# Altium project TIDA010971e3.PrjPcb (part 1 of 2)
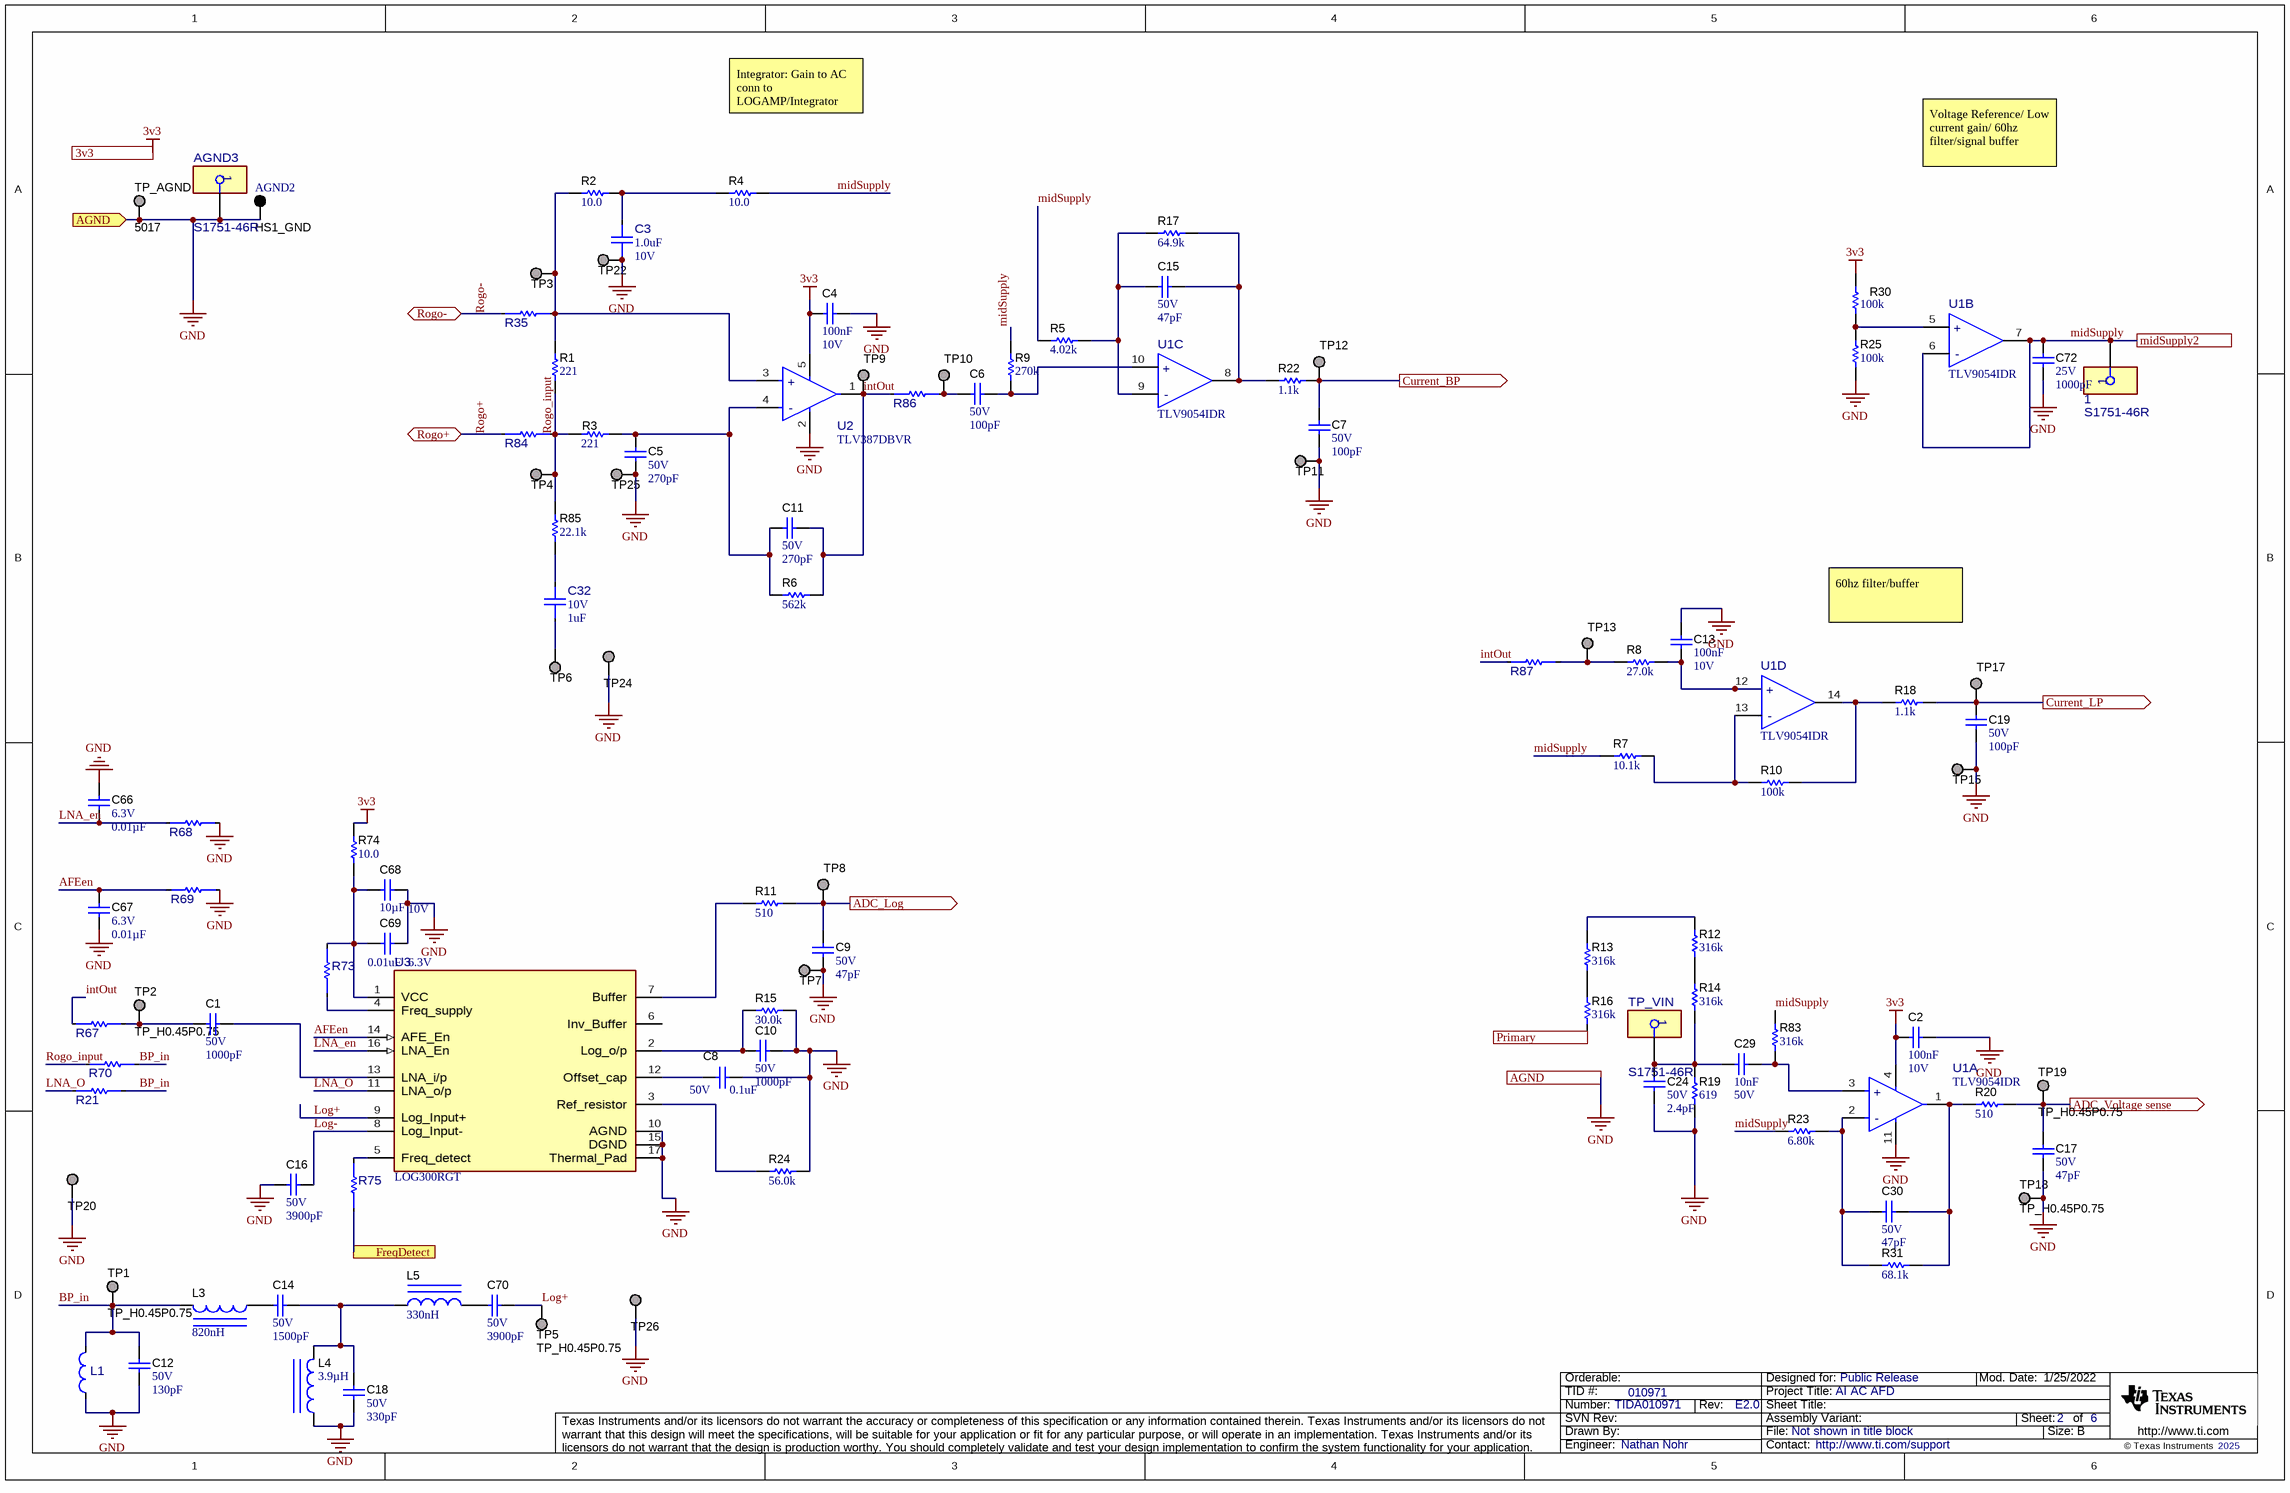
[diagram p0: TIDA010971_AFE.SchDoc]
CopyrightYear: 2025; PCB_Layout: Nathan Nohr; PCB_Rev: E2.2; PRJ_Customer: Public Release; PRJ_Engineer: Nathan Nohr; PRJ_Number: TIDA010971; PRJ_Title: AI AC AFD; SCH_Rev: E2.0; TechSupport: http://www.ti.com/support; TID: 010971
5 sheets, 285 parts. Net scope: flat (ports and power ports of the same name join across sheets).
Board file: TIDA010971_.PcbDoc
Sheets:
  TIDA010971_AFE.SchDoc
  TIDA010971_Hardware.SchDoc
  TIDA010971_Power.SchDoc
  TIDA010971_Connectors_MCU_Labeling.SchDoc
  TIDA010971_AutoLabeling.SchDoc

## Sheet TIDA010971_AFE.SchDoc
size 431 x 279 mm; Date: Not shown in title block; ApprovedBy: Not shown in title block; CheckedBy: Not shown in title block; Author: Not shown in title block; CompanyName: Not shown in title block; Engineer: Not shown in title block; Organization: Not shown in title block; Address1: Not shown in title block; Address2: Not shown in title block; Address3: Not shown in title block; Address4: Not shown in title block; DocumentNumber: 2; Revision: Use project parameter SCH_Rev; SheetNumber: 2; SheetTotal: 6; PageSetup: Record=PageOptions¦CenterHorizontal=True¦CenterVertical=True¦PrintScale=1.00¦XCorrection=1.00¦YCorrection=1.00¦PrintKind=0¦BorderSize=5000000¦LeftOffset=0¦BottomOffset=0¦Orientation=2¦PaperLength=1000¦PaperWidth=1000¦Scale=100¦PaperSource=15¦PrintQuality=600¦MediaType=1¦DitherType=10¦PaperKind=Letter¦PrintScaleMode=1

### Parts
1  S1751-46R  [FP-S1751-46R_SMT_TEST_POINT_3MM25_1MM65-MFG]
AGND2  HS1_GND  [Keystone5006]
AGND3  S1751-46R  [FP-S1751-46R_SMT_TEST_POINT_3MM25_1MM65-MFG]
C1  VDC_V: 50V  ValueDisplayed: 1000pF  [0603]  (hidden comment: GRM1885C1H102JA01D)
C2  Cap_F: 100nF  VDC_V: 10V  [0603]  (hidden comment: 0603ZC104KAT2A)
C3  ValueDisplayed: 1.0uF  VDC_V: 10V  [FP-GRM155Z71A105KE01J_0402-MFG]  (hidden comment: GRM155Z71A105KE01J)
C4  Cap_F: 100nF  VDC_V: 10V  [0603]  (hidden comment: 0603ZC104KAT2A)
C5  VDC_V: 50V  ValueDisplayed: 270pF  [0603]  (hidden comment: C0603C271J5GACTU)
C6  VDC_V: 50V  ValueDisplayed: 100pF  [0603]  (hidden comment: 06035A101JAT2A)
C7  VDC_V: 50V  ValueDisplayed: 100pF  [0603]  (hidden comment: 06035A101JAT2A)
C8  value 0.1uF  VDC_V: 50V  [0603]  (hidden comment: 06035C104JAT2A)
C9  VDC_V: 50V  ValueDisplayed: 47pF  [0603]  (hidden comment: GRM1885C1H470JA01D)
C10  VDC_V: 50V  ValueDisplayed: 1000pF  [0603]  (hidden comment: GRM1885C1H102JA01D)
C11  VDC_V: 50V  ValueDisplayed: 270pF  [0603]  (hidden comment: C0603C271J5GACTU)
C12  VDC_V: 50V  ValueDisplayed: 130pF  [0603]  (hidden comment: GRM1885C1H131JA01D)
C13  Cap_F: 100nF  VDC_V: 10V  [0603]  (hidden comment: 0603ZC104KAT2A)
C14  VDC_V: 50V  ValueDisplayed: 1500pF  [0603]  (hidden comment: GRM1885C1H152JA01D)
C15  VDC_V: 50V  ValueDisplayed: 47pF  [0603]  (hidden comment: 06035A470JAT2A)
C16  VDC_V: 50V  ValueDisplayed: 3900pF  [0402]  (hidden comment: CL05B392KB5NNNC)
C17  VDC_V: 50V  ValueDisplayed: 47pF  [0603]  (hidden comment: GRM1885C1H470JA01D)
C18  VDC_V: 50V  ValueDisplayed: 330pF  [0603]  (hidden comment: GRM1885C1H331JA01D)
C19  VDC_V: 50V  ValueDisplayed: 100pF  [0603]  (hidden comment: 06035A101JAT2A)
C24  VDC_V: 50V  ValueDisplayed: 2.4pF  [0402]  (hidden comment: GRM1555C1H2R4CA01D)
C29  Cap_F: 10nF  VDC_V: 50V  [0603]  (hidden comment: CL10B103KB8NCNC)
C30  VDC_V: 50V  ValueDisplayed: 47pF  [0603]  (hidden comment: GRM1885C1H470JA01D)
C32  VDC_V: 10V  ValueDisplayed: 1uF  [FP-GMC04X7R105K10NT_0402-MFG]  (hidden comment: GMC04X7R105K10NT)
C66  VDC_V: 6.3V  ValueDisplayed: 0.01µF  [0402]  (hidden comment: 0402B103K6R3CT)
C67  VDC_V: 6.3V  ValueDisplayed: 0.01µF  [0402]  (hidden comment: 0402B103K6R3CT)
C68  Cap_F: 10µF  VDC_V: 10V  [0603]  (hidden comment: GRM188Z71A106MA73D)
C69  VDC_V: 6.3V  ValueDisplayed: 0.01uF  [0402]  (hidden comment: GRM155R70J103KA01D)
C70  VDC_V: 50V  ValueDisplayed: 3900pF  [0402]  (hidden comment: CL05B392KB5NNNC)
C72  VDC_V: 25V  ValueDisplayed: 1000pF  [0402]  (hidden comment: C0402C102J3GACTU)
L1  BSCY00160808100MCP  [FP-BSCY00160808100MCP_0603-MFG]  (value not drawn)
L3  ValueDisplayed: 820nH  [0603AF]  (hidden comment: 0603AF-821KRB)
L4  ValueDisplayed: 3.9µH  [0603LS_B2]  (hidden comment: 0603LS-392XJLB)
L5  ValueDisplayed: 330nH  [0603LS_B1]  (hidden comment: 0603LS-331XJLB)
R1  ValueDisplayed: 221  [0603]  (hidden comment: RT0603BRD07221RL)
R2  ValueDisplayed: 10.0  [0603]  (hidden comment: CRCW060310R0FKEAHP)
R3  ValueDisplayed: 221  [0603]  (hidden comment: RG1608P-2210-B-T5)
R4  ValueDisplayed: 10.0  [0603]  (hidden comment: CRCW060310R0FKEAHP)
R5  ValueDisplayed: 4.02k  [0603]  (hidden comment: RT0603DRE074K02L)
R6  ValueDisplayed: 562k  [0603]  (hidden comment: RT0603BRD07562KL)
R7  ValueDisplayed: 10.1k  [0603]  (hidden comment: RT0603DRE0710K1L)
R8  ValueDisplayed: 27.0k  [0603]  (hidden comment: ERJ-3EKF2702V)
R9  ValueDisplayed: 270k  [0603]  (hidden comment: RC0603FR-07270KL)
R10  ValueDisplayed: 100k  [0603]  (hidden comment: CRCW0603100KJNEAC)
R11  ValueDisplayed: 510  [0603]  (hidden comment: RG1608P-511-B-T5)
R12  ValueDisplayed: 316k  [0805_HV1]  (hidden comment: CRCW0805316KFKEA)
R13  ValueDisplayed: 316k  [0805_HV1]  (hidden comment: CRCW0805316KFKEA)
R14  ValueDisplayed: 316k  [0805_HV1]  (hidden comment: CRCW0805316KFKEA)
R15  ValueDisplayed: 30.0k  [0603]  (hidden comment: RC0603FR-0730KL)
R16  ValueDisplayed: 316k  [0805_HV1]  (hidden comment: CRCW0805316KFKEA)
R17  ValueDisplayed: 64.9k  [0603]  (hidden comment: RT0603DRE0764K9L)
R18  ValueDisplayed: 1.1k  [0603]  (hidden comment: CRCW06031K10JNEA)
R19  ValueDisplayed: 619  [0603]  (hidden comment: RC0603FR-07619RL)
R20  ValueDisplayed: 510  [0603]  (hidden comment: RG1608P-511-B-T5)
R21  RC0603FR-100RL  [FP-RC0603FR-100RL_0603-MFG]  (value not drawn)
R22  ValueDisplayed: 1.1k  [0603]  (hidden comment: CRCW06031K10JNEA)
R23  ValueDisplayed: 6.80k  [0603]  (hidden comment: RC0603FR-076K8L)
R24  ValueDisplayed: 56.0k  [0603]  (hidden comment: RG1608P-563-B-T5)
R25  ValueDisplayed: 100k  [0603]  (hidden comment: CRCW0603100KJNEAC)
R30  ValueDisplayed: 100k  [0603]  (hidden comment: CRCW0603100KJNEAC)
R31  ValueDisplayed: 68.1k  [0603]  (hidden comment: RC0603FR-0768K1L)
R35  RC0603FR-100RL  [FP-RC0603FR-100RL_0603-MFG]  (value not drawn)
R67  RC0603FR-100RL  [FP-RC0603FR-100RL_0603-MFG]  (value not drawn)
R68  RC0603FR-100RL  [FP-RC0603FR-100RL_0603-MFG]  (value not drawn)
R69  RC0603FR-100RL  [FP-RC0603FR-100RL_0603-MFG]  (value not drawn)
R70  RC0603FR-100RL  [FP-RC0603FR-100RL_0603-MFG]  (value not drawn)
R73  RC0603FR-100RL  [FP-RC0603FR-100RL_0603-MFG]  (value not drawn)
R74  ValueDisplayed: 10.0  [0402]  (hidden comment: MCR01MZPF10R0)
R75  RC0603FR-100RL  [FP-RC0603FR-100RL_0603-MFG]  (value not drawn)
R83  ValueDisplayed: 316k  [0603]  (hidden comment: RC0603FR-07316KL)
R84  RC0603FR-100RL  [FP-RC0603FR-100RL_0603-MFG]  (value not drawn)
R85  ValueDisplayed: 22.1k  [0603L]  (hidden comment: CRCW060322K1FKEA)
R86  RC0603FR-100RL  [FP-RC0603FR-100RL_0603-MFG]  (value not drawn)
R87  RC0603FR-100RL  [FP-RC0603FR-100RL_0603-MFG]  (value not drawn)
TP1  TP_H0.45P0.75  [TP_H045P075]  (no BOM)
TP2  TP_H0.45P0.75  [TP_H045P075]  (no BOM)
TP3  TP_H0.45P0.75  [TP_H045P075]  (value not drawn)  (no BOM)
TP4  TP_H0.45P0.75  [TP_H045P075]  (value not drawn)  (no BOM)
TP5  TP_H0.45P0.75  [TP_H045P075]  (no BOM)
TP6  TP_H0.45P0.75  [TP_H045P075]  (value not drawn)  (no BOM)
TP7  TP_H0.45P0.75  [TP_H045P075]  (value not drawn)  (no BOM)
TP8  TP_H0.45P0.75  [TP_H045P075]  (value not drawn)  (no BOM)
TP9  TP_H0.45P0.75  [TP_H045P075]  (value not drawn)  (no BOM)
TP10  TP_H0.45P0.75  [TP_H045P075]  (value not drawn)  (no BOM)
TP11  TP_H0.45P0.75  [TP_H045P075]  (value not drawn)  (no BOM)
TP12  TP_H0.45P0.75  [TP_H045P075]  (value not drawn)  (no BOM)
TP13  TP_H0.45P0.75  [TP_H045P075]  (value not drawn)  (no BOM)
TP15  TP_H0.45P0.75  [TP_H045P075]  (value not drawn)  (no BOM)
TP17  TP_H0.45P0.75  [TP_H045P075]  (value not drawn)  (no BOM)
TP18  TP_H0.45P0.75  [TP_H045P075]  (no BOM)
TP19  TP_H0.45P0.75  [TP_H045P075]  (no BOM)
TP20  TP_H0.45P0.75  [TP_H045P075]  (value not drawn)  (no BOM)
TP22  TP_H0.45P0.75  [TP_H045P075]  (value not drawn)  (no BOM)
TP24  TP_H0.45P0.75  [TP_H045P075]  (value not drawn)  (no BOM)
TP25  TP_H0.45P0.75  [TP_H045P075]  (value not drawn)  (no BOM)
TP26  TP_H0.45P0.75  [TP_H045P075]  (value not drawn)  (no BOM)
TP_AGND  5017  [Keystone_5017]
TP_VIN  S1751-46R  [FP-S1751-46R_SMT_TEST_POINT_3MM25_1MM65-MFG]
U1  TLV9054IDR  [D0014A-MFG]  (parts A,B,C,D of 4)
U2  TLV387DBVR  [DBV0005A-MFG]
U3  LOG300RGT  [RGT0016A-MFG]

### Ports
3v3, ADC_Log (out), ADC_Voltage sense (out), AGND, AGND (in), Current_BP (out), Current_LP (out), FreqDetect, midSupply2, Primary, Rogo+ (bidir), Rogo- (bidir)

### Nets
3v3: C2.2 C4.2 R30.2 R74.2 U1.4(V+) U2.5(V+) ; port 3v3
GND: AGND2.1 AGND3.1 C2.1 C3.1 C4.1 C5.1 C7.2 C8.1 C9.2 C10.1 C12.2 C13.1 C16.2 C17.2 C18.2 C19.2 C24.2 C66.1 C67.2 C68.1 C69.1 C72.2 L1.1 L4.1 R15.1 R19.1 R24.2 R25.1 R68.2 R69.1 TP7.1 TP11.1 TP15.1 TP18.1 TP20.1 TP22.1 TP24.1 TP25.1 TP26.1 TP_AGND.1 U1.11(V-) U2.2(V-) U3.10(AGND) U3.15(DGND) U3.17(Thermal_Pad) ; port AGND  [project net AGND]
ADC_Log: C9.1 R11.2 TP8.1 ; port ADC_Log
ADC_Voltage sense: C17.1 R20.2 TP19.1 ; port ADC_Voltage sense
AFEen: C67.1 R69.2 U3.14(AFE_En)
BP_in: C12.1 L1.2 L3.2 R21.2 R70.2 TP1.1
Current_BP: C7.1 R22.2 TP12.1 ; port Current_BP
Current_LP: C19.1 R18.2 TP17.1 ; port Current_LP
FreqDetect: R75.1 ; port FreqDetect
intOut: C11.1 R6.2 R67.1 R86.1 R87.1 TP9.1 U2.1(OUT)
LNA_en: C66.2 R68.1 U3.16(LNA_En)
LNA_O: R21.1 U3.11(LNA_o/p)
Log+: C70.1 TP5.1 U3.9(Log_Input+)
Log-: C16.1 U3.8(Log_Input-)
midSupply: 1.1 C72.1 R4.2 R5.1 R7.1 R9.2 R23.1 R83.2 U1.6(IN2-) U1.7(OUT2) ; port midSupply2
Primary: R16.2 ; port Primary
Rogo+: R84.1 ; port Rogo+
Rogo-: R35.1 ; port Rogo-
Rogo_input: R1.1 R3.1 R70.1 R84.2 R85.2 TP4.1
NetC1_1: C1.1 U3.13(LNA_i/p)
NetC1_2: C1.2 R67.2 TP2.1
NetC3_2: C3.2 R2.2 R4.1
NetC5_2: C5.2 C11.2 R3.2 R6.1 U2.4(-IN)
NetC6_1: C6.1 R9.1 U1.10(IN3+)
NetC6_2: C6.2 R86.2 TP10.1
NetC8_2: C8.2 U3.12(Offset_cap)
NetC10_2: C10.2 R15.2 U3.2(Log_o/p)
NetC13_2: C13.2 R8.2 U1.12(IN4+)
NetC14_1: C14.1 C18.1 L4.2 L5.1
NetC14_2: C14.2 L3.1
NetC15_1: C15.1 R17.2 R22.1 U1.8(OUT3)
NetC15_2: C15.2 R5.2 R17.1 U1.9(IN3-)
NetC24_1: C24.1 C29.2 R14.2 R19.2 TP_VIN.1
NetC29_1: C29.1 R83.1 U1.3(IN1+)
NetC30_1: C30.1 R20.1 R31.2 U1.1(OUT1)
NetC30_2: C30.2 R23.2 R31.1 U1.2(IN1-)
NetC32_1: C32.1 TP6.1
NetC32_2: C32.2 R85.1
NetC68_2: C68.2 C69.2 R73.2 R74.1 U3.1(VCC)
NetC70_2: C70.2 L5.2
NetR1_2: R1.2 R2.1 R35.2 TP3.1 U2.3(+IN)
NetR7_2: R7.2 R10.1 U1.13(IN4-)
NetR8_1: R8.1 R87.2 TP13.1
NetR10_2: R10.2 R18.1 U1.14(OUT4)
NetR11_1: R11.1 U3.7(Buffer)
NetR12_1: R12.1 R13.2
NetR12_2: R12.2 R14.1
NetR13_1: R13.1 R16.1
NetR24_1: R24.1 U3.3(Ref_resistor)
NetR25_2: R25.2 R30.1 U1.5(IN2+)
NetR73_1: R73.1 U3.4(Freq_supply)
NetR75_2: R75.2 U3.5(Freq_detect)

Not connected (* = marked no-connect by the designer): U3 6(Inv_Buffer)

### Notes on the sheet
- Integrator: Gain to AC conn to LOGAMP/Integrator
- Voltage Reference/ Low current gain/ 60hz filter/signal buffer
- 60hz filter/buffer

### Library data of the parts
1 AGND3 TP_VIN = CMP-0089962-1: Natural PC Test Point Brass, Tin Plating Surface Mount Mounting Type; Manufacturer: Harwin; AEC Qualified: No; SizeZ_mm: 2.15mm; Is Female: yes; ContactFinish: Tin,Nickel; Conn Orientation: Vertical; Current_A: 2A
AGND2 = CMP-0055143-2: Test Point, Compact, Black, TH; Manufacturer: Keystone Electronics; CNHeader: FALSE; Green_Lifecycle: Active; Green_REACh: Passed; ContactFinish: Silver; CT: TRUE
C1 C10 = CMP-0007173-4: CAP, CERM, 1000 pF, 50 V, +/- 5%, C0G/NP0, 0603; Manufacturer: MuRata; TaMin_C: -55°C; Polarized: N; SizeAreaWB_mm2: 4.68; Value1: Unknown; U/M: EA; Value: 1000pF; TaMax_C: 125°C; SizeZ_mm: 1; SizeX_mm: 1.6; SizeY_mm: 0.8; SizeArea_mm2: 1.28; Cap_F: 1nF; AEC Category: Q200
C2 C4 C13 = CMP-0006815-4: CAP, CERM, 0.1 uF, 10 V, +/- 10%, X7R, 0603; Manufacturer: AVX; TaMin_C: -55°C; Polarized: N; SizeAreaWB_mm2: 4.68; Value1: Unknown; U/M: EA; Value: 0.1uF; TaMax_C: 125°C; SizeZ_mm: 1; SizeX_mm: 1.6; SizeY_mm: 0.8; SizeArea_mm2: 1.28; AEC Category: Q200
C3 = CMP-0123987-1: Chip Multilayer Ceramic Capacitors for General Purpose, 0402, 1.0uF, X7R, 15%, 10%, 10V; Manufacturer: Murata; AEC Qualified: No; Cap_F: 1µF; SizeZ_mm: 0.6mm; Value: 1µF
C5 C11 = CMP-0006910-4: CAP, CERM, 270 pF, 50 V, +/- 5%, C0G/NP0, 0603; Manufacturer: Kemet; TaMin_C: -55°C; Polarized: N; SizeAreaWB_mm2: 4.68; Value1: Unknown; U/M: EA; Value: 270pF; TaMax_C: 125°C; SizeZ_mm: 1; SizeX_mm: 1.6; SizeY_mm: 0.8; SizeArea_mm2: 1.28; AEC Category: Q200
C6 C7 C19 = CMP-0006763-4: CAP, CERM, 100 pF, 50 V, +/- 5%, C0G/NP0, 0603; Manufacturer: AVX; TaMin_C: -55°C; ESR_ohm: 1.19d; Polarized: N; SizeAreaWB_mm2: 4.68; Value1: 0.119 ohm; U/M: EA; Value: 100pF; TaMax_C: 125°C; SizeZ_mm: 1; SizeX_mm: 1.6; SizeY_mm: 0.8; SizeArea_mm2: 1.28; AEC Category: Q200
C8 = CMP-0083854-1: CAP, CERM, 0.1 µF, 50 V,+/- 5%, X7R, 0603; Manufacturer: AVX; SizeZ_mm: 1; AEC Qualified: N; Cap_F: 100nF; ValueDisplayed: 0.1µF; TaMin_C: -55°C; Green_Lifecycle: Active; SizeAreaWB_mm2: 4.68; Green_REACh: Passed; U/M: EA; TaMax_C: 125°C; SizeX_mm: 1.6; SizeY_mm: 0.8; SizeArea_mm2: 1.28; AEC Category: Q200
C9 C17 C30 = CMP-0007220-4: CAP, CERM, 47 pF, 50 V, +/- 5%, C0G/NP0, 0603; Manufacturer: MuRata; TaMin_C: -55°C; Polarized: N; SizeAreaWB_mm2: 4.68; Value1: Unknown; U/M: EA; Value: 47pF; TaMax_C: 125°C; SizeZ_mm: 1; SizeX_mm: 1.6; SizeY_mm: 0.8; SizeArea_mm2: 1.28; AEC Category: Q200
C12 = CMP-0007182-4: CAP, CERM, 130 pF, 50 V, +/- 5%, C0G/NP0, 0603; Manufacturer: MuRata; TaMin_C: -55°C; Polarized: N; SizeAreaWB_mm2: 4.68; Value1: Unknown; U/M: EA; Value: 130pF; TaMax_C: 125°C; SizeZ_mm: 1; SizeX_mm: 1.6; SizeY_mm: 0.8; SizeArea_mm2: 1.28; AEC Category: Q200
C14 = CMP-0007186-4: CAP, CERM, 1500 pF, 50 V, +/- 5%, C0G/NP0, 0603; Manufacturer: MuRata; TaMin_C: -55°C; Polarized: N; SizeAreaWB_mm2: 4.68; Value1: Unknown; U/M: EA; Value: 1500pF; TaMax_C: 125°C; SizeZ_mm: 1; SizeX_mm: 1.6; SizeY_mm: 0.8; SizeArea_mm2: 1.28; Cap_F: 1.5nF; AEC Category: Q200
C15 = CMP-0006789-4: CAP, CERM, 47 pF, 50 V, +/- 5%, C0G/NP0, 0603; Manufacturer: AVX; TaMin_C: -55°C; ESR_ohm: 1.74d; Polarized: N; SizeAreaWB_mm2: 4.68; Value1: 0.174 ohm; U/M: EA; Value: 47pF; TaMax_C: 125°C; SizeZ_mm: 1; SizeX_mm: 1.6; SizeY_mm: 0.8; SizeArea_mm2: 1.28; AEC Category: Q200
C16 C70 = CMP-0085576-2: CAP, CERM, 3900 pF, 50 V,+/- 10%, X7R, 0402; Manufacturer: Samsung Electro-Mechanics; SizeY_mm: 0.5; AEC Qualified: N; SizeAreaWB_mm2: 3; SizeX_mm: 1; TaMax_C: 125°C; SizeZ_mm: 0.6; Cap_F: 3.9nF; AEC Category: Q200; TaMin_C: -55°C; Value: 3900pF; U/M: EA
C18 = CMP-0007209-4: CAP, CERM, 330 pF, 50 V, +/- 5%, C0G/NP0, 0603; Manufacturer: MuRata; TaMin_C: -55°C; Polarized: N; SizeAreaWB_mm2: 4.68; Value1: Unknown; U/M: EA; Value: 330pF; TaMax_C: 125°C; SizeZ_mm: 1; SizeX_mm: 1.6; SizeY_mm: 0.8; SizeArea_mm2: 1.28; AEC Category: Q200
C24 = CMP-0006449-2: CAP, CERM, 2.4 pF, 50 V, +/- 5%, C0G/NP0, 0402; Manufacturer: MuRata; TaMin_C: -55°C; Polarized: N; SizeAreaWB_mm2: 3; Value1: Unknown; U/M: EA; Value: 2.4pF; TaMax_C: 125°C; SizeZ_mm: 0.6; SizeX_mm: 1; SizeY_mm: 0.5; AEC Category: Q200
C29 = CMP-0007109-5: CAP, CERM, 0.01 uF, 50 V, +/- 10%, X7R, 0603; Manufacturer: Samsung Electro-Mechanics; TaMin_C: -55°C; Polarized: N; SizeAreaWB_mm2: 4.68; Value1: Unknown; U/M: EA; Value: 0.01uF; TaMax_C: 125°C; SizeZ_mm: 1; SizeX_mm: 1.6; SizeY_mm: 0.8; SizeArea_mm2: 1.28; AEC Category: Q200
C32 = CMP-0093200-1: 1µF ±10% 10V Ceramic Capacitor X7R 0402 (1005 Metric); Manufacturer: Cal-Chip Electronics; TempCo: 15%; SizeZ_mm: 0.6mm; AEC Qualified: No
C66 C67 = CMP-0860544-1: CAP, CERM, 0.01 µF, 6.3 V,+/- 10%, X7R, 0402; Manufacturer: Walsin; Value: 0.01uF; SizeY_mm: 0.5; SizeX_mm: 1; SizeZ_mm: 0.6; AEC Category: Q200; SizeAreaWB_mm2: 3; TaMax_C: 125°C; U/M: EA; AEC Qualified: N; Cap_F: 10nF; TaMin_C: -55°C
C68 = CMP-0007497-5: CAP, CERM, 10 uF, 10 V, +/- 20%, X7R, 0603; Manufacturer: MuRata; TaMin_C: -55°C; Polarized: N; SizeAreaWB_mm2: 4.68; Value1: Unknown; U/M: EA; Value: 10uF; TaMax_C: 125°C; SizeZ_mm: 1; SizeX_mm: 1.6; SizeY_mm: 0.8; SizeArea_mm2: 1.28; AEC Category: Q200
C69 = CMP-0006622-2: CAP, CERM, 0.01 uF, 6.3 V, +/- 10%, X7R, 0402; Manufacturer: MuRata; TaMin_C: -55°C; Polarized: N; SizeAreaWB_mm2: 3; Value1: Unknown; U/M: EA; Value: 0.01uF; TaMax_C: 125°C; SizeZ_mm: 0.6; SizeX_mm: 1; SizeY_mm: 0.5; Cap_F: 10nF; AEC Category: Q200
C72 = CMP-0081059-1: CAP, CERM, 1000 pF, 25 V,+/- 5%, C0G/NP0, 0402; Manufacturer: Kemet; TaMin_C: -55°C; Polarized: N; Green_Lifecycle: Active; SizeAreaWB_mm2: 3; Green_REACh: Passed; U/M: EA; Value: 1000pF; TaMax_C: 125°C; SizeZ_mm: 0.6; SizeX_mm: 1; SizeY_mm: 0.5; Cap_F: 1nF; AEC Category: Q200
L1 = CMP-0127583-1: Inductor General Purpose Multi-Layer 10uH 20% 1MHz Ferrite 0.09A 0.9Ohm DCR 0603; Manufacturer: Pulse Electronics; AEC Qualified: No; DCR_ohm: 0.9; Ind_H: 10µH; Irms: 90mA; SizeZ_mm: 1mm
L3 = CMP-0060129-1: Inductor, Wirewound, Ferrite, 820 nH, 0.42 A, 0.579999 ohm, SMD; Manufacturer: Coilcraft; Irms: 0.42A @ 15C rise; Green_Lifecycle: Not Set; SizeAreaWB_mm2: 5.936; DCR_ohm: 5.79999d; Green_REACh: Incomplete; Value: 820nH; Imax_A: 4.2dA; SizeZ_mm: 0.91; SizeX_mm: 1.8; SizeY_mm: 1.12; Value2: 0.42A; SizeArea_mm2: 2.016; AEC Category: Q200
L4 = CMP-0077489-1: Inductor, Wirewound, Ferrite, 3.9 µH, 0.28 A, 1.6 ohm, AEC-Q200 Grade 3, SMD; Manufacturer: Coilcraft; SizeAreaWB_mm2: 6.0732; Irms: 0.28A @ 15C rise; SizeArea_mm2: 2.1042; AEC Qualified: Y; AEC Category: Q200; Value: 3.9uH; SizeZ_mm: 1.12; Imax_A: 2.8dA; AEC Grade: 3; SizeY_mm: 1.169; Value2: 0.28A; Value1: 1.6 ohm; DCR_ohm: 1.6; SizeX_mm: 1.8
L5 = CMP-0077486-1: Inductor, Wirewound, Ferrite, 330 nH, 0.56 A, 0.46 ohm, AEC-Q200 Grade 3, SMD; Manufacturer: Coilcraft; SizeAreaWB_mm2: 5.6448; Irms: 0.56A @ 15C rise; SizeArea_mm2: 1.8288; AEC Qualified: Y; AEC Category: Q200; Value: 330nH; SizeZ_mm: 1.12; Imax_A: 5.6dA; AEC Grade: 3; SizeY_mm: 1.016; Value2: 0.56A; DCR_ohm: 4.6d; SizeX_mm: 1.8
R1 = CMP-0023953-2: RES, 221, 0.1%, 0.1 W, 0603; Manufacturer: Yageo America; Power_W: 100mW; TempCo: 25 ppm/C; Value_Code: 221R; U/M: EA; Value: 221; EIA_Code: E192; SizeX_mm: 1.6; SizeY_mm: 0.8; SizeZ_mm: 1; Value2: 0.1W; SizeArea_mm2: 1.28; VDC_V: 75V; AEC Category: Q200
R2 R4 = CMP-0022004-4: RES, 10.0, 1%, 0.25 W, AEC-Q200 Grade 0, 0603; Manufacturer: Vishay-Dale; Power_W: 250mW; TempCo: 100 ppm/C; Value_Code: 10R0; Value: 10.0; EIA_Code: E96; Res_ohm: 10; SizeX_mm: 1.6; SizeY_mm: 0.8; SizeZ_mm: 1; Value2: 0.25W; SizeArea_mm2: 1.28; AEC Qualified: Y; VDC_V: 75V; AEC Category: Q200; AEC Grade: 0
R3 = CMP-0023468-3: RES, 221, 0.1%, 0.1 W, 0603; Manufacturer: Susumu Co Ltd; Power_W: 100mW; TempCo: 25 ppm/C; Value_Code: 221R; U/M: EA; Value: 221; EIA_Code: E192; SizeX_mm: 1.6; SizeY_mm: 0.8; SizeZ_mm: 1; Value2: 0.1W; SizeArea_mm2: 1.28; VDC_V: 75V; AEC Category: Q200
R5 = CMP-0025335-3: RES, 4.02 k, 0.5%, 0.1 W, 0603; Manufacturer: Yageo America; Power_W: 100mW; TempCo: 50 ppm/C; Value_Code: 4k02; U/M: EA; Value: 4.02k; EIA_Code: E192; SizeX_mm: 1.6; SizeY_mm: 0.8; SizeZ_mm: 1; Value2: 0.1W; SizeArea_mm2: 1.28; VDC_V: 75V; AEC Category: Q200
R6 = CMP-0024341-3: RES, 562 k, 0.1%, 0.1 W, 0603; Manufacturer: Yageo America; Power_W: 100mW; TempCo: 25 ppm/C; U/M: EA; Value: 562k; EIA_Code: E192; SizeX_mm: 1.6; SizeY_mm: 0.8; SizeZ_mm: 1; Value2: 0.1W; SizeArea_mm2: 1.28; VDC_V: 75V; AEC Category: Q200
R7 = CMP-0024579-2: RES, 10.1 k, 0.5%, 0.1 W, 0603; Manufacturer: Yageo America; Power_W: 100mW; TempCo: 50 ppm/C; Value_Code: 10k1; U/M: EA; Value: 10.1k; EIA_Code: E192; SizeX_mm: 1.6; SizeY_mm: 0.8; SizeZ_mm: 1; Value2: 0.1W; SizeArea_mm2: 1.28; VDC_V: 75V; AEC Category: Q200
R8 = CMP-0022694-3: RES, 27.0 k, 1%, 0.1 W, AEC-Q200 Grade 0, 0603; Manufacturer: Panasonic; Power_W: 100mW; TempCo: 100 ppm/C; Value_Code: 27k0; U/M: EA; Value: 27.0k; Res_ohm: 27k; SizeX_mm: 1.6; SizeY_mm: 0.8; SizeZ_mm: 1; Value2: 0.1W; SizeArea_mm2: 1.28; AEC Qualified: Y; VDC_V: 50V; AEC Grade: 0; AEC Category: Q200
R9 = CMP-0022961-4: RES, 270 k, 1%, 0.1 W, 0603; Manufacturer: Yageo; Power_W: 100mW; TempCo: 100 ppm/C; Value: 270k; SizeX_mm: 1.6; SizeY_mm: 0.8; SizeZ_mm: 1; Value2: 0.1W; SizeArea_mm2: 1.28; AEC Qualified: N; VDC_V: 75V; AEC Category: Q200; SizeAreaWB_mm2: 4.68
R10 R25 R30 = CMP-0082530-1: RES, 100 k, 5%, 0.1 W, 0603; Manufacturer: Vishay-Dale; Power_W: 100mW; TempCo: 200 ppm/C; SizeAreaWB_mm2: 4.68; Value: 100k; EIA_Code: E24; SizeX_mm: 1.6; SizeY_mm: 0.8; SizeZ_mm: 1; Value2: 0.1W; SizeArea_mm2: 1.28; AEC Qualified: N; VDC_V: 75V; AEC Category: Q200
R11 R20 = CMP-0023567-3: RES, 510, 0.1%, 0.1 W, 0603; Manufacturer: Susumu Co Ltd; Power_W: 100mW; TempCo: 25 ppm/C; Value_Code: 510R; U/M: EA; Value: 510; SizeX_mm: 1.6; SizeY_mm: 0.8; SizeZ_mm: 1; Value2: 0.1W; SizeArea_mm2: 1.28; VDC_V: 75V; AEC Category: Q200
R12-R14 R16 = CMP-0021166-3: RES, 316 k, 1%, 0.125 W, AEC-Q200 Grade 0, 0805; Manufacturer: Vishay-Dale; Power_W: 125mW; TempCo: 100 ppm/C; Value: 316k; EIA_Code: E96; SizeX_mm: 2; SizeY_mm: 1.25; SizeZ_mm: 1.45; Value2: 0.125W; SizeArea_mm2: 2.5; AEC Qualified: Y; VDC_V: 150V; AEC Category: Q200; AEC Grade: 0
R15 = CMP-0023020-5: RES, 30.0 k, 1%, 0.1 W, 0603; Manufacturer: Yageo; Power_W: 100mW; TempCo: 100 ppm/C; Value_Code: 30k0; Value: 30.0k; Res_ohm: 30k; SizeX_mm: 1.6; SizeY_mm: 0.8; SizeZ_mm: 1; Value2: 0.1W; SizeArea_mm2: 1.28; AEC Qualified: N; VDC_V: 75V; AEC Category: Q200; SizeAreaWB_mm2: 4.68
R17 = CMP-0025488-3: RES, 64.9 k, 0.5%, 0.1 W, 0603; Manufacturer: Yageo America; Power_W: 100mW; TempCo: 50 ppm/C; Value_Code: 64k9; U/M: EA; Value: 64.9k; EIA_Code: E192; SizeX_mm: 1.6; SizeY_mm: 0.8; SizeZ_mm: 1; Value2: 0.1W; SizeArea_mm2: 1.28; VDC_V: 75V; AEC Category: Q200
R18 R22 = CMP-0025730-4: RES, 1.1 k, 5%, 0.1 W, AEC-Q200 Grade 0, 0603; Manufacturer: Vishay-Dale; Power_W: 100mW; TempCo: 200 ppm/C; Value_Code: 1k10; Value: 1.1k; EIA_Code: E24; SizeX_mm: 1.6; SizeY_mm: 0.8; SizeZ_mm: 1; Value2: 0.1W; SizeArea_mm2: 1.28; AEC Qualified: Y; VDC_V: 75V; AEC Category: Q200; AEC Grade: 0
R19 = CMP-0023215-5: RES, 619, 1%, 0.1 W, 0603; Manufacturer: Yageo; Power_W: 100mW; TempCo: 100 ppm/C; Value_Code: 619R; Value: 619; EIA_Code: E96; SizeX_mm: 1.6; SizeY_mm: 0.8; SizeZ_mm: 1; Value2: 0.1W; SizeArea_mm2: 1.28; AEC Qualified: N; VDC_V: 75V; AEC Category: Q200; SizeAreaWB_mm2: 4.68
R21 R35 R67-R70 R73 R75 R84 R86 R87 = CMP-0123755-1: 0 Ohms Jumper Chip Resistor 0603 (1608 Metric) Moisture Resistant Thick Film; Manufacturer: Yageo; AEC Qualified: No; Res_ohm: 0; SizeZ_mm: 0.55mm; Tolerance_%: 1%; Value: 0
R23 = CMP-0023253-5: RES, 6.80 k, 1%, 0.1 W, 0603; Manufacturer: Yageo; Power_W: 100mW; TempCo: 100 ppm/C; Value_Code: 6k80; Value: 6.80k; Res_ohm: 6.8k; SizeX_mm: 1.6; SizeY_mm: 0.8; SizeZ_mm: 1; Value2: 0.1W; SizeArea_mm2: 1.28; AEC Qualified: N; VDC_V: 75V; AEC Category: Q200; SizeAreaWB_mm2: 4.68
R24 = CMP-0023577-3: RES, 56.0 k, 0.1%, 0.1 W, 0603; Manufacturer: Susumu Co Ltd; Power_W: 100mW; TempCo: 25 ppm/C; Value_Code: 56k0; U/M: EA; Value: 56.0k; Res_ohm: 56k; SizeX_mm: 1.6; SizeY_mm: 0.8; SizeZ_mm: 1; Value2: 0.1W; SizeArea_mm2: 1.28; VDC_V: 75V; AEC Category: Q200
R31 = CMP-0023238-5: RES, 68.1 k, 1%, 0.1 W, 0603; Manufacturer: Yageo; Power_W: 100mW; TempCo: 100 ppm/C; Value_Code: 68k1; Value: 68.1k; EIA_Code: E96; SizeX_mm: 1.6; SizeY_mm: 0.8; SizeZ_mm: 1; Value2: 0.1W; SizeArea_mm2: 1.28; AEC Qualified: N; VDC_V: 75V; AEC Category: Q200; SizeAreaWB_mm2: 4.68
R74 = CMP-0026717-1: RES, 10.0, 1%, 0.063 W, 0402; Manufacturer: Rohm; Power_W: 63mW; TempCo: 100 ppm/C; Value_Code: 10R0; U/M: EA; Value: 10.0; EIA_Code: E96; Res_ohm: 10; SizeX_mm: 1; SizeY_mm: 0.5; SizeZ_mm: 0.6; Value2: 0.063W; AEC Qualified: N; VDC_V: 50V; AEC Category: Q200
R83 = CMP-0023024-4: RES, 316 k, 1%, 0.1 W, 0603; Manufacturer: Yageo; Power_W: 100mW; TempCo: 100 ppm/C; Value: 316k; EIA_Code: E96; SizeX_mm: 1.6; SizeY_mm: 0.8; SizeZ_mm: 1; Value2: 0.1W; SizeArea_mm2: 1.28; AEC Qualified: N; VDC_V: 75V; AEC Category: Q200; SizeAreaWB_mm2: 4.68
R85 = CMP-0022220-4: RES, 22.1 k, 1%, 0.1 W, AEC-Q200 Grade 0, 0603; Manufacturer: Vishay-Dale; Power_W: 100mW; TempCo: 100 ppm/C; Value_Code: 22k1; Value: 22.1k; EIA_Code: E96; SizeX_mm: 1.6; SizeY_mm: 0.8; SizeZ_mm: 1; Value2: 0.1W; SizeArea_mm2: 1.28; AEC Qualified: Y; VDC_V: 75V; AEC Category: Q200; AEC Grade: 0
TP1-TP13 TP15 TP17-TP20 TP22 TP24-TP26 = CMP-0003719-1: Testpoint; Manufacturer: Texas Instruments; CompType: Pad
TP_AGND = CMP-0078225-3: PC Test Point, SMT; Manufacturer: Keystone Electronics
U1 = CMP-0125179-1: Quad 5-MHz, 15-V/µs high slew-rate, RRIO op amp 14-SOIC -40 to 125; Manufacturer: Texas Instruments; SizeZ_mm: 1.75mm; AEC Qualified: No; Gain Bandwidth: 5MHz; Input Bias Current: 2pA; Input Offset Voltage: 0.33mV; Max Dual Supply Voltage: 3V; Max Supply Voltage: 6V; Min Dual Supply Voltage: 900mV; Min Supply Voltage: 1.8V; Nominal Supply Current: 330uA; Number Of Channels: 4; Output Current Per Channel: 50mA; Response Time: 1us; Standoff Height: 0.1mm; TaMax_C: +125°C; TaMin_C: -40°C; TJmax_C: +150°C; Voltage Gain: 130dB
U2 = CMP-0125353-1: Zero-Drift Amplifier 1 Circuit Rail-to-Rail SOT-23-5; Manufacturer: Texas Instruments; SizeZ_mm: 1.45mm; AEC Qualified: No; Gain Bandwidth: 5.7MHz; Input Bias Current: 60pA; Input Offset Voltage: 1.25uV; Max Dual Supply Voltage: 2.75V; Max Supply Voltage: 5.5V; Min Dual Supply Voltage: 850mV; Min Supply Voltage: 1.7V; Nominal Supply Current: 570uA; Number Of Channels: 1; Output Current Per Channel: 55mA; Response Time: 2.5us; Standoff Height: 0mm; TaMax_C: +125°C; TaMin_C: -40°C; TJmax_C: +150°C; Voltage Gain: 145dB
U3 = CMP-0122050-1: 80-MHz, Logarithmic Detector With Integrated Low-Noise Amplifier; Manufacturer: Texas Instruments; SizeZ_mm: 1mm; AEC Qualified: No; Bandwidth: 79.9999MHz; Max Supply Voltage: 5.25V; Min Supply Voltage: 3V; Standoff Height: 0mm; TaMax_C: +125°C; TaMin_C: -40°C; TJmax_C: +150°C

## Sheet TIDA010971_Hardware.SchDoc
size 431 x 279 mm; Date: Not shown in title block; ApprovedBy: Not shown in title block; CheckedBy: Not shown in title block; Author: Not shown in title block; CompanyName: Not shown in title block; Engineer: Not shown in title block; Organization: Not shown in title block; Address1: Not shown in title block; Address2: Not shown in title block; Address3: Not shown in title block; Address4: Not shown in title block; DocumentNumber: 3; Revision: Use project parameter SCH_Rev; SheetNumber: 3; SheetTotal: 6; PageSetup: Record=PageOptions¦CenterHorizontal=True¦CenterVertical=True¦PrintScale=1.00¦XCorrection=1.00¦YCorrection=1.00¦PrintKind=0¦BorderSize=5000000¦LeftOffset=0¦BottomOffset=0¦Orientation=2¦PaperLength=1000¦PaperWidth=1000¦Scale=100¦PaperSource=15¦PrintQuality=600¦MediaType=1¦DitherType=10¦PaperKind=Letter¦PrintScaleMode=1
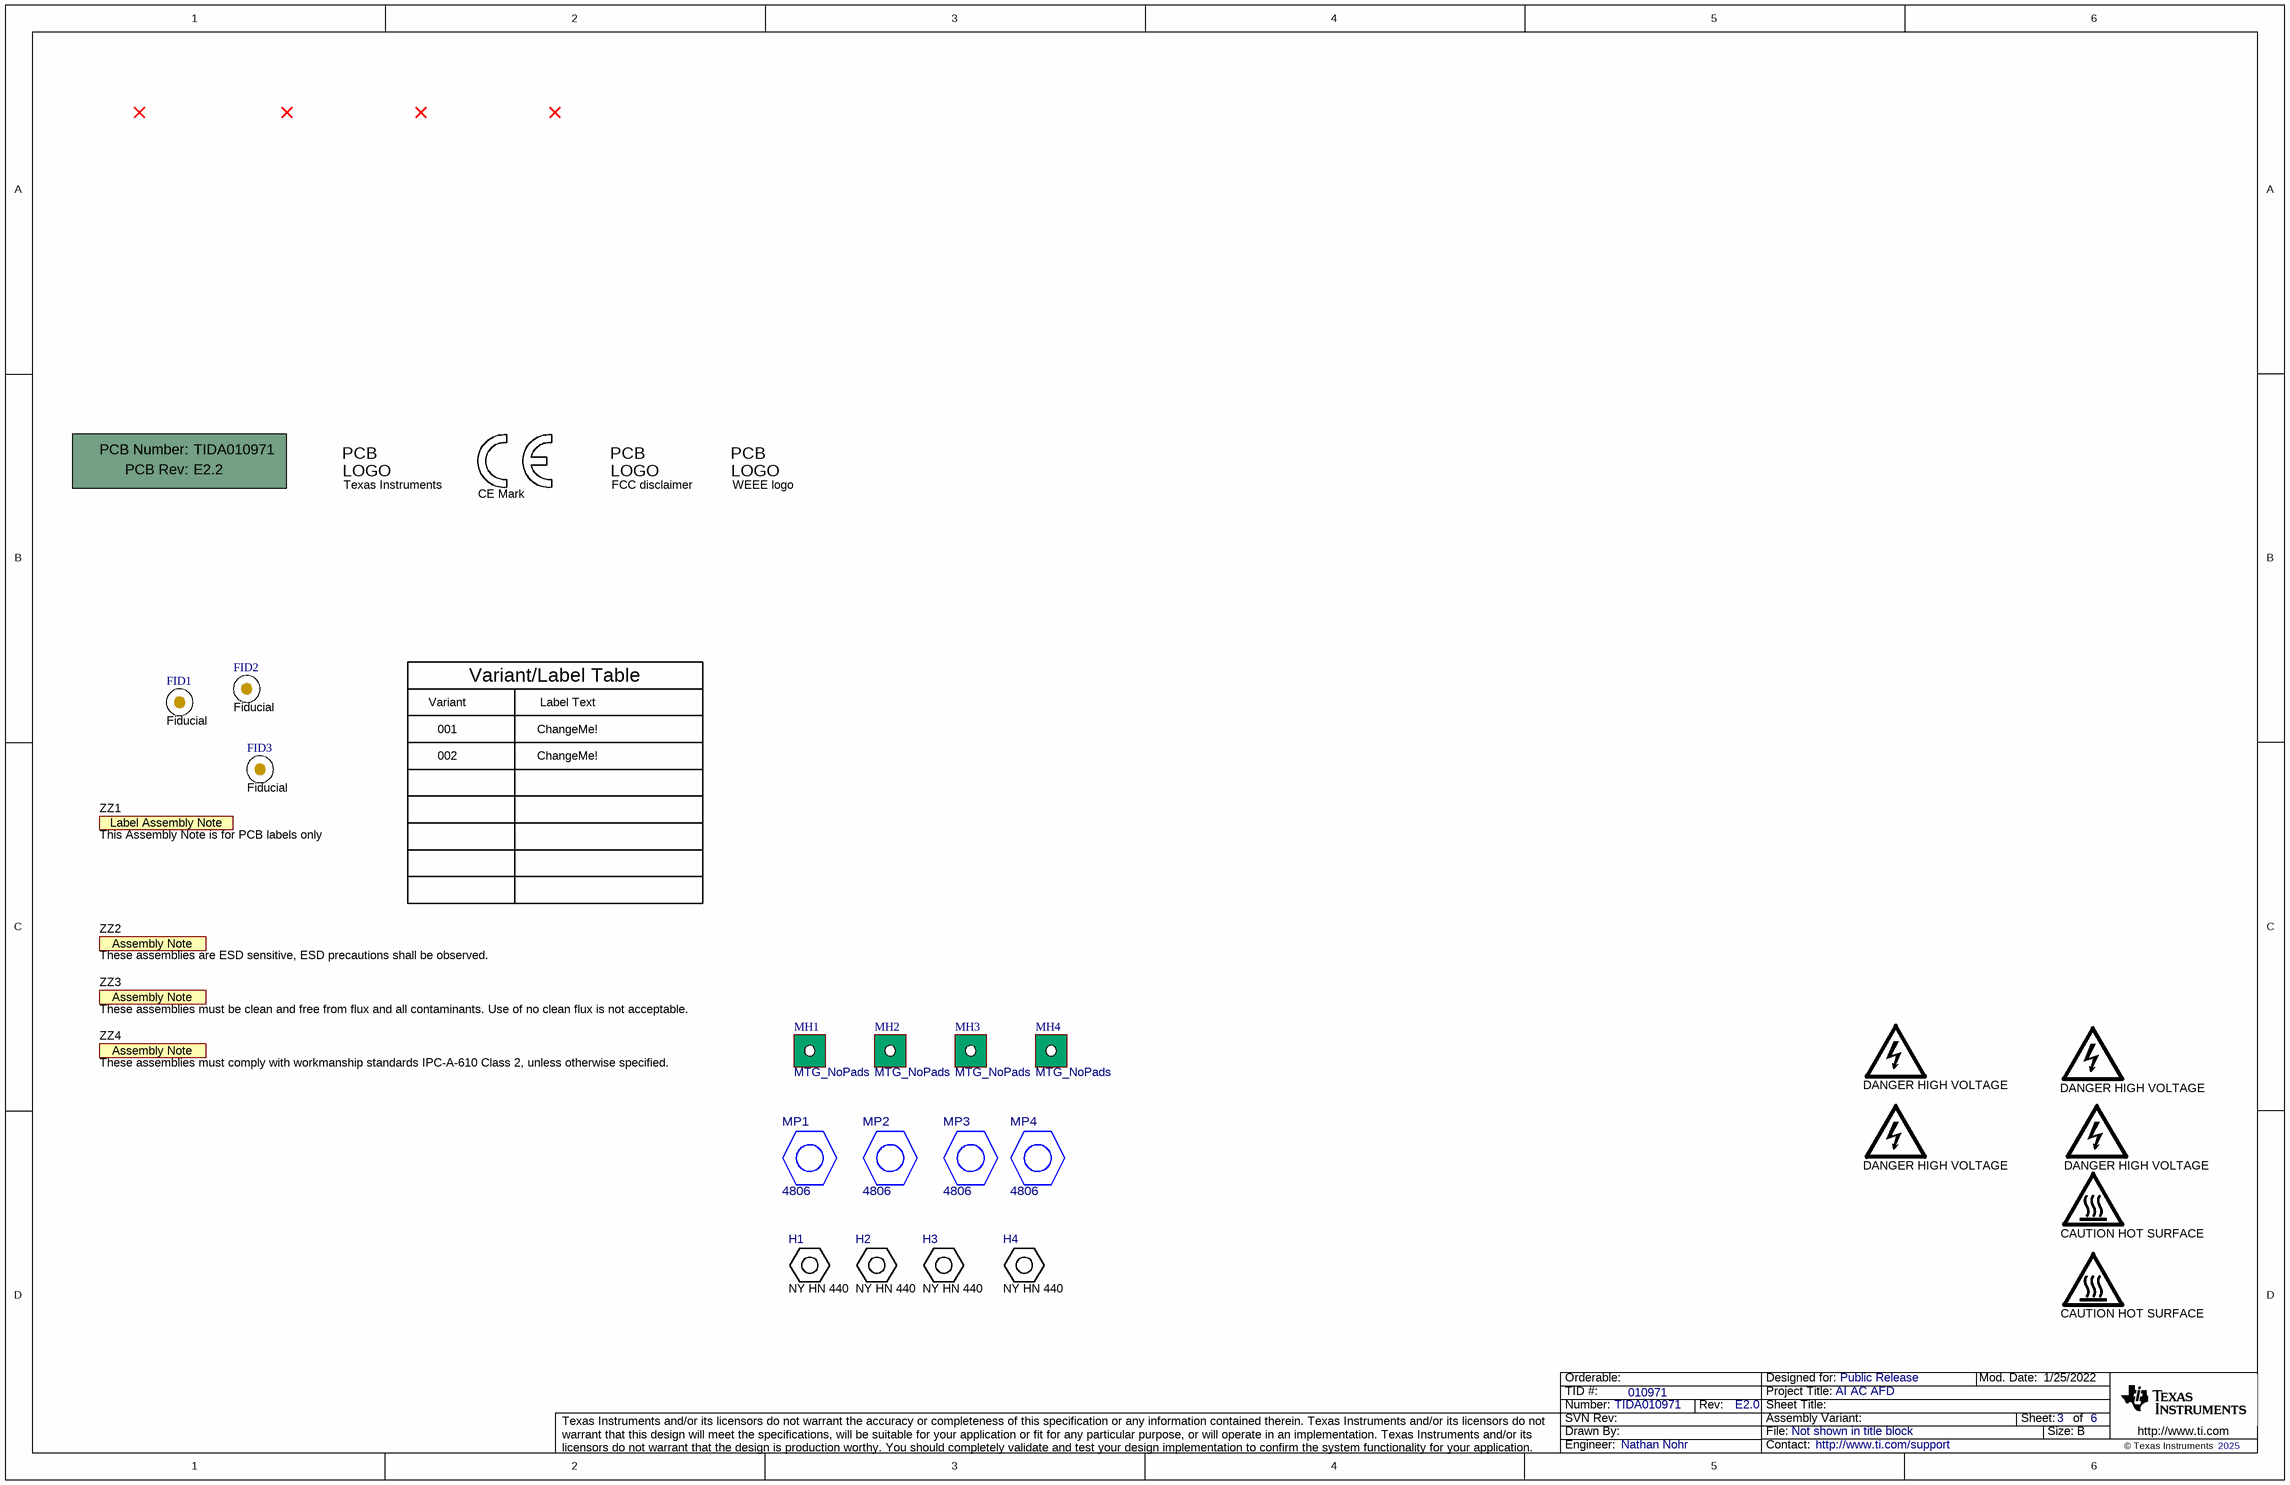
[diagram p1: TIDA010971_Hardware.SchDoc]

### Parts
!PCB  Printed Circuit Board  (value not drawn)  (mechanical)
FID1  Fiducial  [Fiducial10-30]
FID2  Fiducial  [Fiducial10-30]
FID3  Fiducial  [Fiducial10-30]
H1  NY HN 440  (mechanical)
H2  NY HN 440  (mechanical)
H3  NY HN 440  (mechanical)
H4  NY HN 440  (mechanical)
Logo1  Texas Instruments  [TI_Stacked_Overlay_Small]  (no BOM)
Logo2  CE Mark  [CE_Mark_5mm]  (no BOM)
Logo3  FCC disclaimer  [FCC_disclaimer]  (no BOM)
Logo4  WEEE logo  [WEEE_Minimum]  (no BOM)
LOGO5  DANGER HIGH VOLTAGE  [IEC_HighVoltage_Small]  (no BOM)
LOGO6  DANGER HIGH VOLTAGE  [IEC_HighVoltage_Small]  (no BOM)
LOGO7  CAUTION HOT SURFACE  [IEC_HotSurface_Small]  (no BOM)
LOGO8  DANGER HIGH VOLTAGE  [IEC_HighVoltage_Small]  (no BOM)
LOGO9  CAUTION HOT SURFACE  [IEC_HotSurface_Small]  (no BOM)
LOGO10  DANGER HIGH VOLTAGE  [IEC_HighVoltage_Small]  (no BOM)
MH1  MTG_NoPads  [NPTH125mil]  (no BOM)
MH2  MTG_NoPads  [NPTH125mil]  (no BOM)
MH3  MTG_NoPads  [NPTH125mil]  (no BOM)
MH4  MTG_NoPads  [NPTH125mil]  (no BOM)
MP1  4806  [FP-4806_HEX_STNDFF_4-40-MFG]
MP2  4806  [FP-4806_HEX_STNDFF_4-40-MFG]
MP3  4806  [FP-4806_HEX_STNDFF_4-40-MFG]
MP4  4806  [FP-4806_HEX_STNDFF_4-40-MFG]
ZZ1  This Assembly Note is for PCB labels only  [AssemblyNoteLabel]  (no BOM)
ZZ2  These assemblies are ESD sensitive, ESD precautions shall be observed.  [AssemblyNote]  (no BOM)
ZZ3  These assemblies must be clean and free from flux and all contaminants. Use of no clean flux is not acceptable.  [AssemblyNote]  (no BOM)
ZZ4  These assemblies must comply with workmanship standards IPC-A-610 Class 2, unless otherwise specified.  [AssemblyNote]  (no BOM)

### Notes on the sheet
- Variant
- Variant/Label Table
- Label Text
- 001
- 002
- ChangeMe!

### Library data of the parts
!PCB = CMP-0003618-2: Manufacturer: Any; PartNumber: TIDA010971
FID1-FID3 = CMP-0077181-1: Fiducial mark.  There is nothing to buy or mount.
H1-H4 = CMP-0003666-1: Nut, Hex, 4-40, Nylon; Manufacturer: B&F Fastener Supply; CompType: Hardware
Logo1 = CMP-0074838-1: Texas Instrument Corporate Signature; SymbolCreator: a0412235; Lib Reference: TI_Logo; Library Reference: Logo
Logo2 = CMP-0074844-1: SymbolCreator: a0412235
Logo3 = CMP-0074847-1: FCC_disclaimer; Library Reference: Logo
Logo4 = CMP-0074769-1
LOGO5 LOGO6 LOGO8 LOGO10 = CMP-0074835-1: IEC 61010-1 High Voltage Warning; SymbolCreator: a0412235; Lib Reference: IEC_HighVoltage
LOGO7 LOGO9 = CMP-0074837-1: IEC 61010-1 Hot Surface Warning; SymbolCreator: a0412235; Lib Reference: IEC_HotSurface
MH1-MH4 = CMP-0078424-2: PCB Mounting Hole, No Pad; Manufacturer: Any; Key: Mounting Hole (non-standard) No Pad
MP1-MP4 = CMP-0122442-1: Hex Standoff Threaded #4-40 Nylon 1.000" (25.40mm) 1" Natural; Manufacturer: Keystone; AEC Qualified: No; SizeZ_mm: 25.78mm
ZZ1 = CMP-0003616-3
ZZ2 = CMP-0077236-1
ZZ3 = CMP-0077237-1
ZZ4 = CMP-0077238-1

## Sheet TIDA010971_Power.SchDoc
size 431 x 279 mm; Date: Not shown in title block; ApprovedBy: Not shown in title block; CheckedBy: Not shown in title block; Author: Not shown in title block; CompanyName: Not shown in title block; Engineer: Not shown in title block; Organization: Not shown in title block; Address1: Not shown in title block; Address2: Not shown in title block; Address3: Not shown in title block; Address4: Not shown in title block; DocumentNumber: 2; Revision: Use project parameter SCH_Rev; SheetNumber: 4; SheetTotal: 6; PageSetup: Record=PageOptions¦CenterHorizontal=True¦CenterVertical=True¦PrintScale=1.00¦XCorrection=1.00¦YCorrection=1.00¦PrintKind=0¦BorderSize=5000000¦LeftOffset=0¦BottomOffset=0¦Orientation=2¦PaperLength=1000¦PaperWidth=1000¦Scale=100¦PaperSource=15¦PrintQuality=600¦MediaType=1¦DitherType=10¦PaperKind=Letter¦PrintScaleMode=1
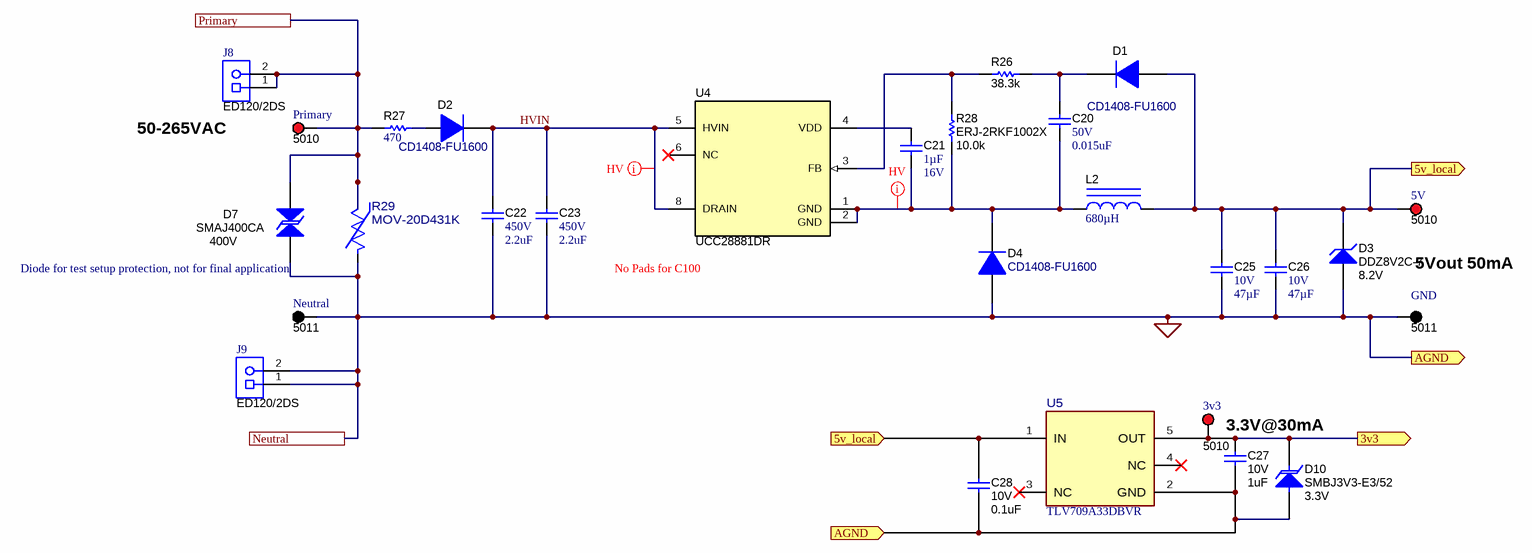
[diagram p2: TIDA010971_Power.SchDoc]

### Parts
3v3  5010  [Keystone5010]
5V  5010  [Keystone5010]
C20  VDC_V: 50V  ValueDisplayed: 0.015uF  [0402S]  (hidden comment: GRM155R71H153KA12D)
C21  ValueDisplayed: 1µF  VDC_V: 16V  [0402]  (hidden comment: GRM155R61C105MA12D)
C22  VDC_V: 450V  ValueDisplayed: 2.2uF  [CKG57N]  (hidden comment: CKG57NX7T2W225M500JH)
C23  VDC_V: 450V  ValueDisplayed: 2.2uF  [CKG57N]  (hidden comment: CKG57NX7T2W225M500JH)
C25  VDC_V: 10V  ValueDisplayed: 47µF  [0805L]  (hidden comment: GRM21BR61A476ME15L)
C26  VDC_V: 10V  ValueDisplayed: 47µF  [0805L]  (hidden comment: GRM21BR61A476ME15L)
C27  VDC_V: 10V  ValueDisplayed: 1uF  [0402S]  (hidden comment: GRM155R61A105ME15D)
C28  VDC_V: 10V  ValueDisplayed: 0.1uF  [0402S]  (hidden comment: GRM155R61A104KA01D)
D1  CD1408-FU1600  [Diode_1408]
D2  CD1408-FU1600  [Diode_1408]
D3  DDZ8V2C-7  value 8.2V  [SOD-123]
D4  CD1408-FU1600  [Diode_1408]
D7  SMAJ400CA  value 400V  [SMA_Bi]
D10  SMBJ3V3-E3/52  value 3.3V  [SMB]
GND  5011  [Keystone5011]
J8  ED120/2DS  [On-Shore_ED120_2DS]
J9  ED120/2DS  [On-Shore_ED120_2DS]
L2  ValueDisplayed: 680µH  [WE-LQ_1812]  (hidden comment: 744045681)
Neutral  5011  [Keystone5011]
Primary  5010  [Keystone5010]
R26  ValueDisplayed: 38.3k  [0402S]  (hidden comment: CRCW040238K3FKED)
R27  ValueDisplayed: 470  [2010L]  (hidden comment: CRCW2010470RFKEF)
R28  ERJ-2RKF1002X  ValueDisplayed: 10.0k  [0402S]
R29  MOV-20D431K  [FP-MOV-20D431K_RADIAL-MFG]
U4  UCC28881DR  [D0007A_N]
U5  TLV709A33DBVR  [DBV0005A-MFG]

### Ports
3v3 (out), 5v_local (in), 5v_local (out), AGND (in), AGND (out), Neutral, Primary

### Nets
3v3: 3v3.1 C27.1 D10.1(K) U5.5(OUT) ; port 3v3
AGND: C22.2 C23.2 C25.2 C26.2 C27.2 C28.2 D3.2(A) D4.2(A) D7.1 D10.2(A) GND.1 J9.1 J9.2 Neutral.1 R29.1 U5.2(GND) ; port AGND, port Neutral
5v_led: 5V.1 C25.1 C26.1 C28.1 D1.2(A) D3.1(K) L2.2 U5.1(IN) ; port 5v_local
HVIN: C22.1 C23.1 D2.1(K) U4.5(HVIN) U4.8(DRAIN)
Primary: D7.2 J8.1 J8.2 Primary.1 R27.1 R29.2 ; port Primary
NetC20_1: C20.1 D1.1(K) R26.2
NetC20_2: C20.2 C21.2 D4.1(K) L2.1 R28.1 U4.1(GND) U4.2(GND)
NetC21_1: C21.1 U4.4(VDD)
NetD2_2: D2.2(A) R27.2
NetR26_1: R26.1 R28.2 U4.3(FB)

Not connected (* = marked no-connect by the designer): U4 6(NC)*; U5 3(NC)* 4(NC)*

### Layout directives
net class HV: HVIN, NetC20_2

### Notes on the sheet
- (near J8) 50-265VAC
- (near R29) Diode for test setup protection, not for final application
- (near U4) No Pads for C100
- 5Vout 50mA
- 3.3V@30mA

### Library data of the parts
3v3 5V Primary = CMP-0055147-2: Test Point, Multipurpose, Red, TH; Manufacturer: Keystone Electronics; CT: TRUE; ContactFinish: Silver; Green_Lifecycle: Active; CNHeader: FALSE; Green_REACh: Passed
C20 = CMP-0006679-2: CAP, CERM, 0.015 uF, 50 V, +/- 10%, X7R, 0402; Manufacturer: MuRata; TaMin_C: -55°C; Polarized: N; SizeAreaWB_mm2: 3; Value1: Unknown; U/M: EA; TaMax_C: 125°C; SizeZ_mm: 0.6; SizeX_mm: 1; SizeY_mm: 0.5; Cap_Case: 0402; Cap_F: 15nF; AEC Category: Q200
C21 = CMP-0084375-1: CAP, CERM, 1 µF, 16 V,+/- 20%, X5R, 0402; Manufacturer: MuRata; SizeX_mm: 1; AEC Category: Q200; SizeAreaWB_mm2: 3; U/M: EA; TaMin_C: -55°C; AEC Qualified: N; SizeZ_mm: 0.6; TaMax_C: 85°C; SizeArea_mm2: 0.5; Value: 1uF
C22 C23 = CMP-0009428-2: CAP, CERM, 2.2 uF, 450 V, +/- 20%, X7T, AEC-Q200 Grade 1, 6x5x5mm; Manufacturer: TDK; TaMin_C: -55°C; Polarized: N; SizeAreaWB_mm2: 56; Value1: Unknown; U/M: EA; Value: 2.2uF; TaMax_C: 125°C; SizeZ_mm: 5.5; SizeX_mm: 6; SizeY_mm: 5; Cap_Case: 2220; SizeArea_mm2: 30; AEC Qualified: Y; Cap_F: 2.2µF; AEC Grade: 1; AEC Category: Q200
C25 C26 = CMP-0078699-1: CAP, CERM, 47 µF, 10 V,+/- 20%, X5R, 0805; Manufacturer: MuRata; TaMin_C: -55°C; Polarized: N; Green_Lifecycle: Active; SizeAreaWB_mm2: 6.75; Green_REACh: Passed; U/M: EA; Value: 47uF; TaMax_C: 85°C; SizeZ_mm: 1.45; SizeX_mm: 2; SizeY_mm: 1.25; Cap_Case: 0805; SizeArea_mm2: 2.5; AEC Category: Q200
C27 = CMP-0064927-2: CAP, CERM, 1 uF, 10 V,+/- 20%, X5R, 0402; Manufacturer: MuRata; TaMin_C: -55°C; Polarized: N; SizeAreaWB_mm2: 3; Value1: Unknown; U/M: EA; Value: 1uF; TaMax_C: 85°C; SizeZ_mm: 0.6; SizeX_mm: 1; SizeY_mm: 0.5; Cap_Case: 0402; Cap_F: 1µF; AEC Category: Q200
C28 = CMP-0006562-2: CAP, CERM, 0.1 uF, 10 V, +/- 10%, X5R, 0402; Manufacturer: MuRata; TaMin_C: -55°C; Polarized: N; SizeAreaWB_mm2: 3; Value1: Unknown; U/M: EA; Value: 0.1uF; TaMax_C: 85°C; SizeZ_mm: 0.6; SizeX_mm: 1; SizeY_mm: 0.5; Cap_Case: 0402; Cap_F: 100nF; AEC Category: Q200
D1 D2 D4 = CMP-0029015-1: Diode, Ultrafast, 600 V, 1 A, 1408 Diode; Manufacturer: Bourns; Io_A: 1A; Green_Lifecycle: Not Set; SizeAreaWB_mm2: 12.76; Vr_V: 600V; Green_REACh: Incomplete; TJmax_C: 175°C; U/M: EA; Value: 600V; SizeZ_mm: 1.15; SizeX_mm: 3.4; SizeY_mm: 1.9; Vf_V: 1.25V; SizeArea_mm2: 6.46; AEC Qualified: N; AEC Category: Q101; RJC_CperW: 40
D3 = CMP-0085110-1: Diode, Zener, 8.2 V, 500 mW, SOD-123; Manufacturer: Diodes Inc.; SizeAreaWB_mm2: 13.095; RJA_CperW: 425; SizeX_mm: 3.85; Value1: 0.5W; AEC Qualified: N; Power_W: 500mW; SizeY_mm: 1.7; AEC Category: Q101; SizeZ_mm: 1.35; SizeArea_mm2: 6.545
D7 = CMP-0085045-1: Diode, TVS, Bi, 400 V, 648 Vc, 400 W, 0.6 A, SMA (non-polarized); Manufacturer: Littelfuse; SizeArea_mm2: 13.068125; SizeAreaWB_mm2: 32.368125; Value1: 648V; Vbr_Min: 447V; AEC Qualified: N; SizeX_mm: 5.075; SizeY_mm: 2.575; Ipp: 600mA; AEC Category: Q101; RJA_CperW: 120; SizeZ_mm: 2.65; Vbr_Max: 494V; Ppk: 400W
D10 = CMP-0005592-3: Diode, TVS, Uni, 3.3 V, 7.3 Vc, AEC-Q101, SMB; Manufacturer: Vishay-Semiconductor; SizeZ_mm: 2.6; Ipp: 50A; Vc: 7.3V; Vbr_Min: 4.1V; SizeY_mm: 3.81; SizeAreaWB_mm2: 44.156; AEC Qualified: Y; SizeArea_mm2: 21.336; RJA_CperW: 100; SizeX_mm: 5.6; Value1: 600W; AEC Category: Q101
GND Neutral = CMP-0055148-2: Test Point, Multipurpose, Black, TH; Manufacturer: Keystone Electronics; CNHeader: FALSE; ContactFinish: Silver; Green_REACh: Passed; Green_Lifecycle: Active; CT: TRUE
J8 J9 = CMP-0074910-1: Terminal Block, 5.08 mm, 2x1, Brass, TH; Manufacturer: On-Shore Technology; Cert_VDE: Y; CNHeader: False; Current_A: 15A; Green_Lifecycle: Not Set; Shrouded: N; Gender: Female; Green_REACh: Incomplete; Voltage_V: 300V; Row_Count: 1; Pitch_mm: 5.08; CT: True
L2 = CMP-0084743-1: Inductor, Wirewound, Ferrite, 680 µH, 0.09 A, 16.8 ohm, SMD; Manufacturer: Wurth Elektronik; Imax_A: 90mA; AEC Category: Q200; Isat: 0.2A @ 20% inductance drop; SizeZ_mm: 2.9; SizeY_mm: 3.2; Value: 680uH; Value2: 0.09A; DCR_ohm: 16.8; SizeX_mm: 4.5; Irms: 0.09A @ 40C rise; SizeArea_mm2: 14.4; SizeAreaWB_mm2: 23.1; AEC Qualified: N
R26 = CMP-0026323-1: RES, 38.3 k, 1%, 0.063 W, 0402; Manufacturer: Vishay-Dale; Power_W: 63mW; TempCo: 100 ppm/C; Value_Code: 38k3; U/M: EA; Value: 38.3k; EIA_Code: E96; SizeX_mm: 1; SizeY_mm: 0.5; SizeZ_mm: 0.6; Value2: 0.063W; VDC_V: 50V; AEC Category: Q200
R27 = CMP-0016409-3: RES, 470, 1%, 0.75 W, AEC-Q200 Grade 0, 2010; Manufacturer: Vishay-Dale; Power_W: 750mW; TempCo: 100 ppm/C; Value_Code: 470R; Value: 470; SizeX_mm: 5; SizeY_mm: 2.5; SizeZ_mm: 1.66; Value2: 0.75W; SizeArea_mm2: 12.5; AEC Qualified: Y; VDC_V: 400V; AEC Grade: 0; AEC Category: Q200
R28 = CMP-0026658-1: RES, 10.0 k, 1%, 0.1 W, 0402; Manufacturer: Panasonic; Power_W: 100mW; TempCo: 100 ppm/C; Value_Code: 10k0; U/M: EA; Value: 10.0k; EIA_Code: E96; Res_ohm: 10k; SizeX_mm: 1; SizeY_mm: 0.5; SizeZ_mm: 0.6; Value2: 0.1W; VDC_V: 50V; AEC Category: Q200
R29 = CMP-0092774-1: 430 V 6.5 kA Varistor 1 Circuit Through Hole Disc 20mm; Manufacturer: Bourns Inc.; SizeZ_mm: 26mm; Cap_F: 1116pF; Clamping Voltage: 710V; AEC Qualified: No; Vc: 100A; Voltage Tolerance: 10%; Varistor Voltage: 387V; VDC_V: 350V
U4 = CMP-0074092-2: 700-V Lowest Quiescent Current Off-Line Switcher, D0007A (SOIC-7); Alternate Manufacturer: Texas Instruments; SizeAreaWB_mm2: 55.2; U/M: EA; SizeZ_mm: 1.75; SizeX_mm: 6.0; SizeY_mm: 4.9; SizeArea_mm2: 29.4; CompType: IC; AEC Category: Q200; AEC Qualified: N
U5 = CMP-0034271-1: 150-mA 30-V low-dropout (LDO) linear regulator with 3.2-μA supply current 5-SOT-23 -40 to 125; Manufacturer: Texas Instruments; SizeZ_mm: 1.45mm; AEC Qualified: No; Accuracy Percentage: 4%; Dropout Voltage: 1000mV; Max Supply Voltage: 30V; Min Supply Voltage: 4.3V; Nominal Supply Current: 3.2uA; Number Of Outputs: 1; Output Type: Fixed; Output Voltage: 3.3V; Standoff Height: 0mm; TJmax_C: +125°C

## Sheet TIDA010971_Connectors_MCU_Labeling.SchDoc
size 431 x 279 mm; Date: Not shown in title block; ApprovedBy: Not shown in title block; CheckedBy: Not shown in title block; Author: Not shown in title block; CompanyName: Not shown in title block; Engineer: Not shown in title block; Organization: Not shown in title block; Address1: Not shown in title block; Address2: Not shown in title block; Address3: Not shown in title block; Address4: Not shown in title block; DocumentNumber: 2; Revision: Use project parameter SCH_Rev; SheetNumber: 5; SheetTotal: 6; PageSetup: Record=PageOptions¦CenterHorizontal=True¦CenterVertical=True¦PrintScale=1.00¦XCorrection=1.00¦YCorrection=1.00¦PrintKind=0¦BorderSize=5000000¦LeftOffset=0¦BottomOffset=0¦Orientation=2¦PaperLength=1000¦PaperWidth=1000¦Scale=100¦PaperSource=15¦PrintQuality=600¦MediaType=1¦DitherType=10¦PaperKind=Letter¦PrintScaleMode=1
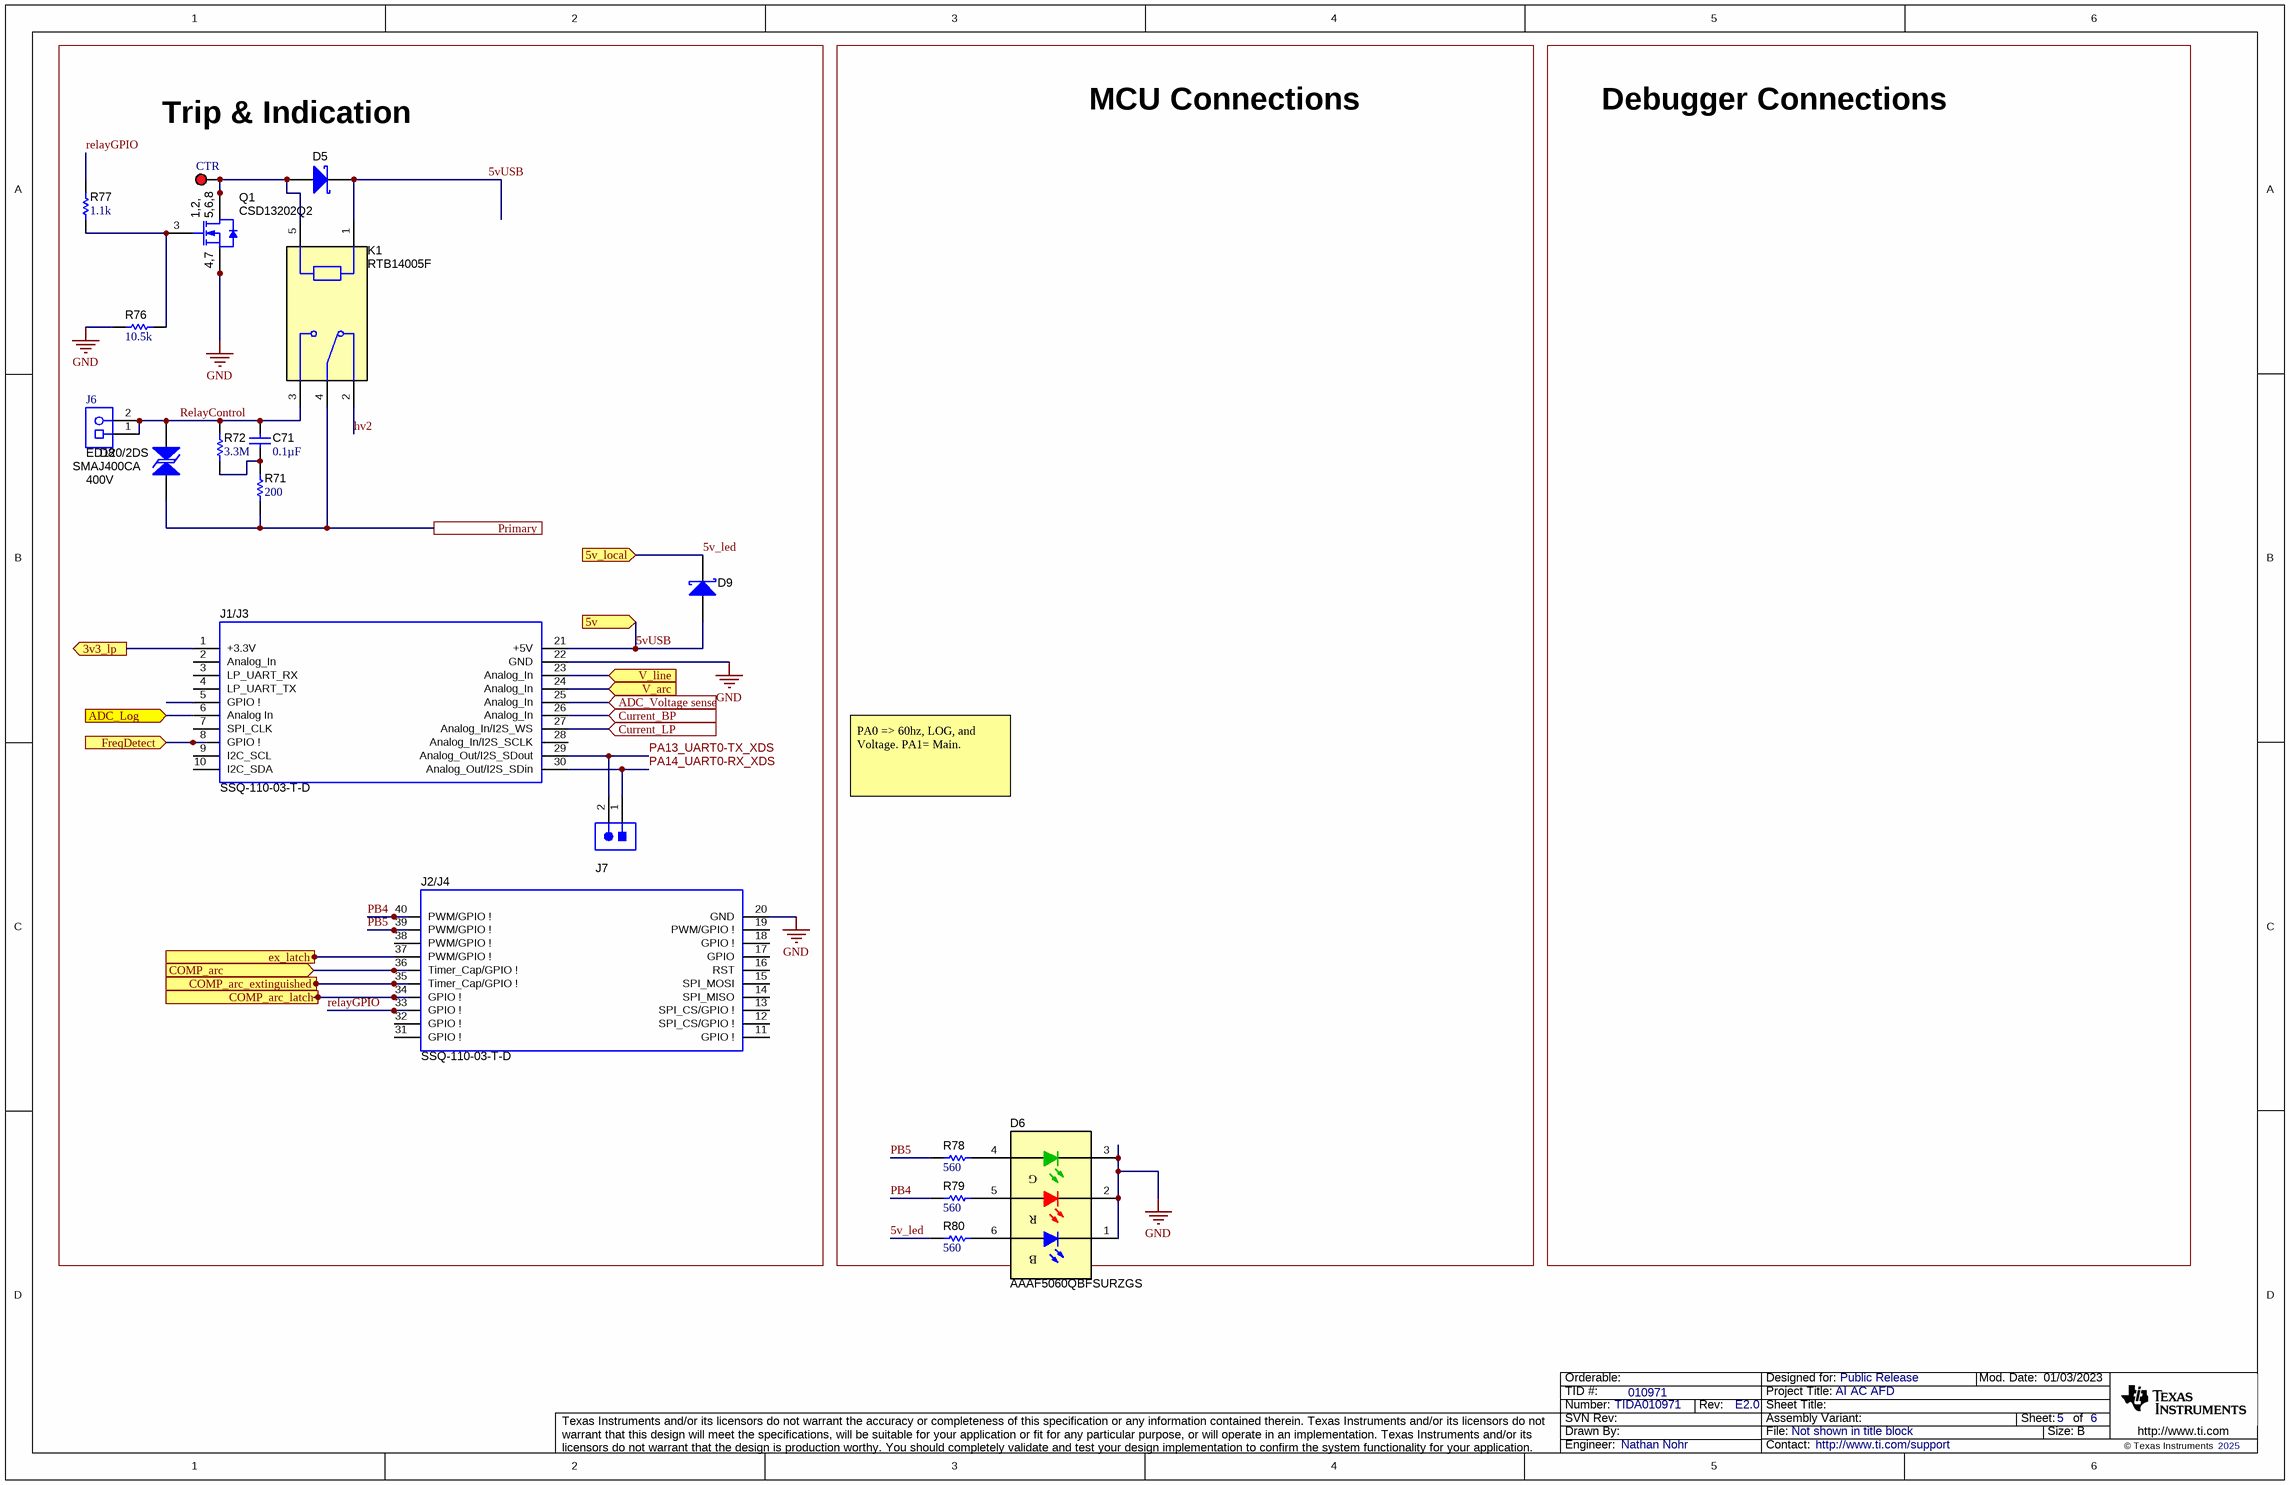
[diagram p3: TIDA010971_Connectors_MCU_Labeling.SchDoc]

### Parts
C71  ValueDisplayed: 0.1µF  [B32933_600x1500x2650]  (hidden comment: B32933A3104K000)
CTR  (no value)  [Keystone5005]
D5  (no value)  [DO-219AB]
D6  AAAF5060QBFSURZGS  [AAAF5060QBFSURZGS]
D8  SMAJ400CA  value 400V  [SMA_Bi]
D9  (no value)  [DO-219AB]
J1/J3  SSQ-110-03-T-D  [BoosterPack_40pin_J1J3]
J2/J4  SSQ-110-03-T-D  [BoosterPack_40pin_J2J4]
J6  ED120/2DS  [On-Shore_ED120_2DS]
J7  TSW-102-07-G-S  [TSW-102-07-G-S]  (value not drawn)
K1  RTB14005F  [RELAY_RTB14]
Q1  CSD13202Q2  [DQK0006C]
R71  ValueDisplayed: 200  [2512]  (hidden comment: CRM2512-FX-2000ELF)
R72  ValueDisplayed: 3.3M  [1210]  (hidden comment: RC1210JR-073M3L)
R76  ValueDisplayed: 10.5k  [0603]  (hidden comment: RT0603DRE0710K5L)
R77  ValueDisplayed: 1.1k  [0603]  (hidden comment: RC0603JR-071K1L)
R78  ValueDisplayed: 560  [0603]  (hidden comment: RC0603JR-07560RL)
R79  ValueDisplayed: 560  [0603]  (hidden comment: RC0603JR-07560RL)
R80  ValueDisplayed: 560  [0603]  (hidden comment: RC0603JR-07560RL)

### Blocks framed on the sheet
Trip & Indication: C71 CTR D5 D8 D9 J1/J3 J2/J4 J6 J7 K1 Q1 R71 R72 R76 R77
MCU Connections: D6 R78-R80

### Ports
3v3_lp (out), 5v (in), 5v_local (in), ADC_Log (in), ADC_Voltage sense (in), COMP_arc (in), COMP_arc_extinguished (in), COMP_arc_latch (in), Current_BP (in), Current_LP (in), ex_latch (in), FreqDetect (in), Primary, V_arc (in), V_line (in)

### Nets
3v3USB: J1/J3.1(+3.3V) ; port 3v3_lp
GND: D6.1(K) D6.2(K) D6.3(K) J1/J3.22(GND) J2/J4.20(GND) Q1.4(S) Q1.7(S) R76.1  [project net AGND]
5v_led: D9.1(K) R80.1 ; port 5v_local
5vUSB: D5.1(K) D9.2(A) J1/J3.21(+5V) K1.1 ; port 5v
ADC_Log: J1/J3.6(Analog_In) ; port ADC_Log
ADC_Voltage sense: J1/J3.25(Analog_In) ; port ADC_Voltage sense
COMP_arc_extinguished: J2/J4.35(Timer_Cap/GPIO_!) ; port COMP_arc_extinguished
COMP_VGap: J2/J4.36(Timer_Cap/GPIO_!) ; port COMP_arc
COMP_VGap_LATCH: J2/J4.34(GPIO_!) ; port COMP_arc_latch
Current_BP: J1/J3.26(Analog_In) ; port Current_BP
Current_LP: J1/J3.27(Analog_In/I2S_WS) ; port Current_LP
ex_latch: J2/J4.37(PWM/GPIO_!) ; port ex_latch
FreqDetect: J1/J3.8(GPIO_!) ; port FreqDetect
hv2: K1.2
PA13_UART0-TX_XDS: J1/J3.29(Analog_Out/I2S_SDout) J7.2
PA14_UART0-RX_XDS: J1/J3.30(Analog_Out/I2S_SDin) J7.1
PB4: J2/J4.40(PWM/GPIO_!) R79.1
PB5: J2/J4.39(PWM/GPIO_!) R78.1
Primary: D8.1 K1.4 R71.1 ; port Primary
RelayControl: C71.2 D8.2 J6.1 J6.2 K1.3 R72.2
relayGPIO: J2/J4.33(GPIO_!) R77.2
V_Gap: J1/J3.24(Analog_In) ; port V_arc
V_String: J1/J3.23(Analog_In) ; port V_line
NetC71_1: C71.1 R71.2 R72.1
NetCTR_1: CTR.1 D5.2(A) K1.5 Q1.1(D) Q1.2(D) Q1.5(D) Q1.6(D) Q1.8(D)
NetD6_4: D6.4(A) R78.2
NetD6_5: D6.5(A) R79.2
NetD6_6: D6.6(A) R80.2
NetQ1_3: Q1.3(G) R76.2 R77.1

Not connected (* = marked no-connect by the designer): J1/J3 2(Analog_In) 3(LP_UART_RX) 4(LP_UART_TX) 5(GPIO_!) 7(SPI_CLK) 9(I2C_SCL) 10(I2C_SDA) 28(Analog_In/I2S_SCLK); J2/J4 11(GPIO_!) 12(SPI_CS/GPIO_!) 13(SPI_CS/GPIO_!) 14(SPI_MISO) 15(SPI_MOSI) 16(RST) 17(GPIO) 18(GPIO_!) 19(PWM/GPIO_!) 31(GPIO_!) 32(GPIO_!) 38(PWM/GPIO_!)

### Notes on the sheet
- Debugger Connections
- PA0 => 60hz, LOG, and Voltage. PA1= Main.

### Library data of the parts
C71 = CMP-0077664-2: CAP, Film, 0.1 µF, X2 305 VAC, +/- 10%, AEC-Q200 Grade 2, TH; Manufacturer: TDK; TaMin_C: -40°C; Polarized: N; SizeAreaWB_mm2: 210.0; Value: 0.1uF; TaMax_C: 105°C; VAC_X: 305; SizeZ_mm: 15.0; SizeX_mm: 26.0; SizeY_mm: 5.5; SizeArea_mm2: 143.0; AEC Qualified: Y; Cap_F: 100nF; AEC Grade: 2; AEC Category: Q200
CTR = CMP-0055142-2: Test Point, Compact, Red, TH; Manufacturer: Keystone Electronics; CNHeader: FALSE; Green_Lifecycle: Active; Green_REACh: Passed; ContactFinish: Silver; CT: TRUE
D5 D9 = CMP-0028636-3: Diode, Schottky, 20 V, 1.1 A, DO-219AB; PartNumber: SL02-GS08; Manufacturer: Vishay-Semiconductor; Vr_V: 20V; TJmax_C: 125°C; SizeX_mm: 3.7; Vf_V: 420mV; Value1: 1.1A; SizeZ_mm: 1.08; SizeArea_mm2: 6.66; AEC Category: Q101; SizeAreaWB_mm2: 13.16; Green_Lifecycle: Not Set; Green_REACh: Incomplete; Value: 20V; SizeY_mm: 1.8; Value2: 0.42V
D6 = CMP-0078806-2: LED, RGB, SMD; Manufacturer: Kingbright; Vr_V: 5V; Angle: 100; Tjmax_C: 85°C; SizeArea_mm2: 34.2; Value2: 3.3V; SizeZ_mm: 2.3; SizeX_mm: 5.7; SizeAreaWB_mm2: 61.6; Power_TotalModule: 350mW; Ir_A: 50µA; Value1: 0.35W; Io_A: 20mA; SizeY_mm: 6; Type: InGaN
D8 = CMP-0085045-1: as D7 on sheet TIDA010971_Power
J1/J3 = CMP-0003837-4: Receptacle, 2.54mm, 10x2, Tin, TH; Alternate PartNumber: CRD-081413-A-G; Manufacturer: Samtec; Alternate Manufacturer: Major League Electronics; Note: Booster Pack 40 pin J1 and J3; Green_Lifecycle: Active; Green_REACh: Incomplete
J2/J4 = CMP-0078266-4: Receptacle, 2.54mm, 10x2, Tin, TH; Alternate PartNumber: CRD-081413-A-G; Manufacturer: Samtec; Alternate Manufacturer: Major League Electronics; Note: Booster Pack 40 pin J2 and J4; Green_REACh: Incomplete; Green_Lifecycle: Active
J6 = CMP-0074910-1: as J8 on sheet TIDA010971_Power
J7 = CMP-0075405-2: Header, 100mil, 2x1, Gold, TH; Manufacturer: Samtec; Pitch_mm: 2.54; Cert_VDE: N; Gender: Male; Cert_CSA: Y; Voltage_V: 550V; Green_REACh: Passed; Current_A: 6.3A; Green_Lifecycle: Active; Row_Count: 1
K1 = CMP-0002574-2: Relay, SPDT ( 1 Form C), 12 A, 5 V, TH; Manufacturer: Tyco Electronics; Contact Rating_A: 12A; Turn On Voltage (Max)_VDC: 3.5V; Coil Power_W: 403mW; Coil Resistance_ohm: 62; Time Operate (s): 8ms; Coil Current_A: 80mA; Turn Off Voltage (Min)_VDC: 5dV; Coil Type: Non Latching; Time Release (s): 6ms; Coil Voltage_VDC: 5V
Q1 = CMP-0000193-1: MOSFET, N-CH, 12 V, 22 A, DQK0006C (WSON-6); Alternate Manufacturer: None; Manufacturer: Texas Instruments; SizeZ_mm: 0.8; ChType: N; Value2: 5.1 nC; Value1: 0.009; VdsMax_V: 12V; SizeX_mm: 2; Vgs_V: 8V; Value: 12V; Rdson45_ohm: 9.3m; SizeArea_mm2: 4; AEC Category: Q101; IdsMax_A: 22A; SizeAreaWB_mm2: 9; U/M: EA; QgTyp_nC: 5.1
R71 = CMP-0078952-1: RES, 200, 1%, 2 W, 2512; Manufacturer: Bourns; Value_Code: 200R; SizeArea_mm2: 20.16; AEC Qualified: N; AEC Category: Q200; Value: 200; SizeZ_mm: 0.71; EIA_Code: E96; TempCo: 100 ppm/C; Power_W: 2W; VDC_V: 300V; SizeY_mm: 3.2; SizeX_mm: 6.3
R72 = CMP-0083544-1: RES, 3.3 M, 5%, 0.5 W, 1210; Manufacturer: Yageo; Power_W: 500mW; TempCo: 100 ppm/C; SizeAreaWB_mm2: 14.7; Value_Code: 3M30; Value: 3.3Meg; EIA_Code: E24; SizeX_mm: 3.2; SizeY_mm: 2.5; SizeZ_mm: 1.35; Value2: 0.5W; SizeArea_mm2: 8; AEC Qualified: N; VDC_V: 200V; AEC Category: Q200
R76 = CMP-0024582-3: RES, 10.5 k, 0.5%, 0.1 W, 0603; Manufacturer: Yageo America; Power_W: 100mW; TempCo: 50 ppm/C; Value_Code: 10k5; U/M: EA; Value: 10.5k; EIA_Code: E192; SizeX_mm: 1.6; SizeY_mm: 0.8; SizeZ_mm: 1; Value2: 0.1W; SizeArea_mm2: 1.28; VDC_V: 75V; AEC Category: Q200
R77 = CMP-0025893-5: RES, 1.1 k, 5%, 0.1 W, 0603; Manufacturer: Yageo; Power_W: 100mW; TempCo: 100 ppm/C; Value_Code: 1k10; Value: 1.1k; EIA_Code: E24; SizeX_mm: 1.6; SizeY_mm: 0.8; SizeZ_mm: 1; Value2: 0.1W; SizeArea_mm2: 1.28; AEC Qualified: N; VDC_V: 75V; AEC Category: Q200; SizeAreaWB_mm2: 4.68
R78-R80 = CMP-0025930-5: RES, 560, 5%, 0.1 W, 0603; Manufacturer: Yageo; Power_W: 100mW; TempCo: 100 ppm/C; Value_Code: 560R; Value: 560; EIA_Code: E24; SizeX_mm: 1.6; SizeY_mm: 0.8; SizeZ_mm: 1; Value2: 0.1W; SizeArea_mm2: 1.28; AEC Qualified: N; VDC_V: 75V; AEC Category: Q200; SizeAreaWB_mm2: 4.68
